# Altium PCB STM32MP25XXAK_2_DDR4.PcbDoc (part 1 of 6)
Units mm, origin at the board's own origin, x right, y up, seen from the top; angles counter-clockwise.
Board outline 120 x 79.6 mm, 4 copper layers (Top Layer, Signal Layer 1, Signal Layer 2, Bottom Layer), stack 1.614 mm thick; 243 components, 152 nets, 1304 pads, 784 vias.
Unrouted connection lines stored in the file: 6.
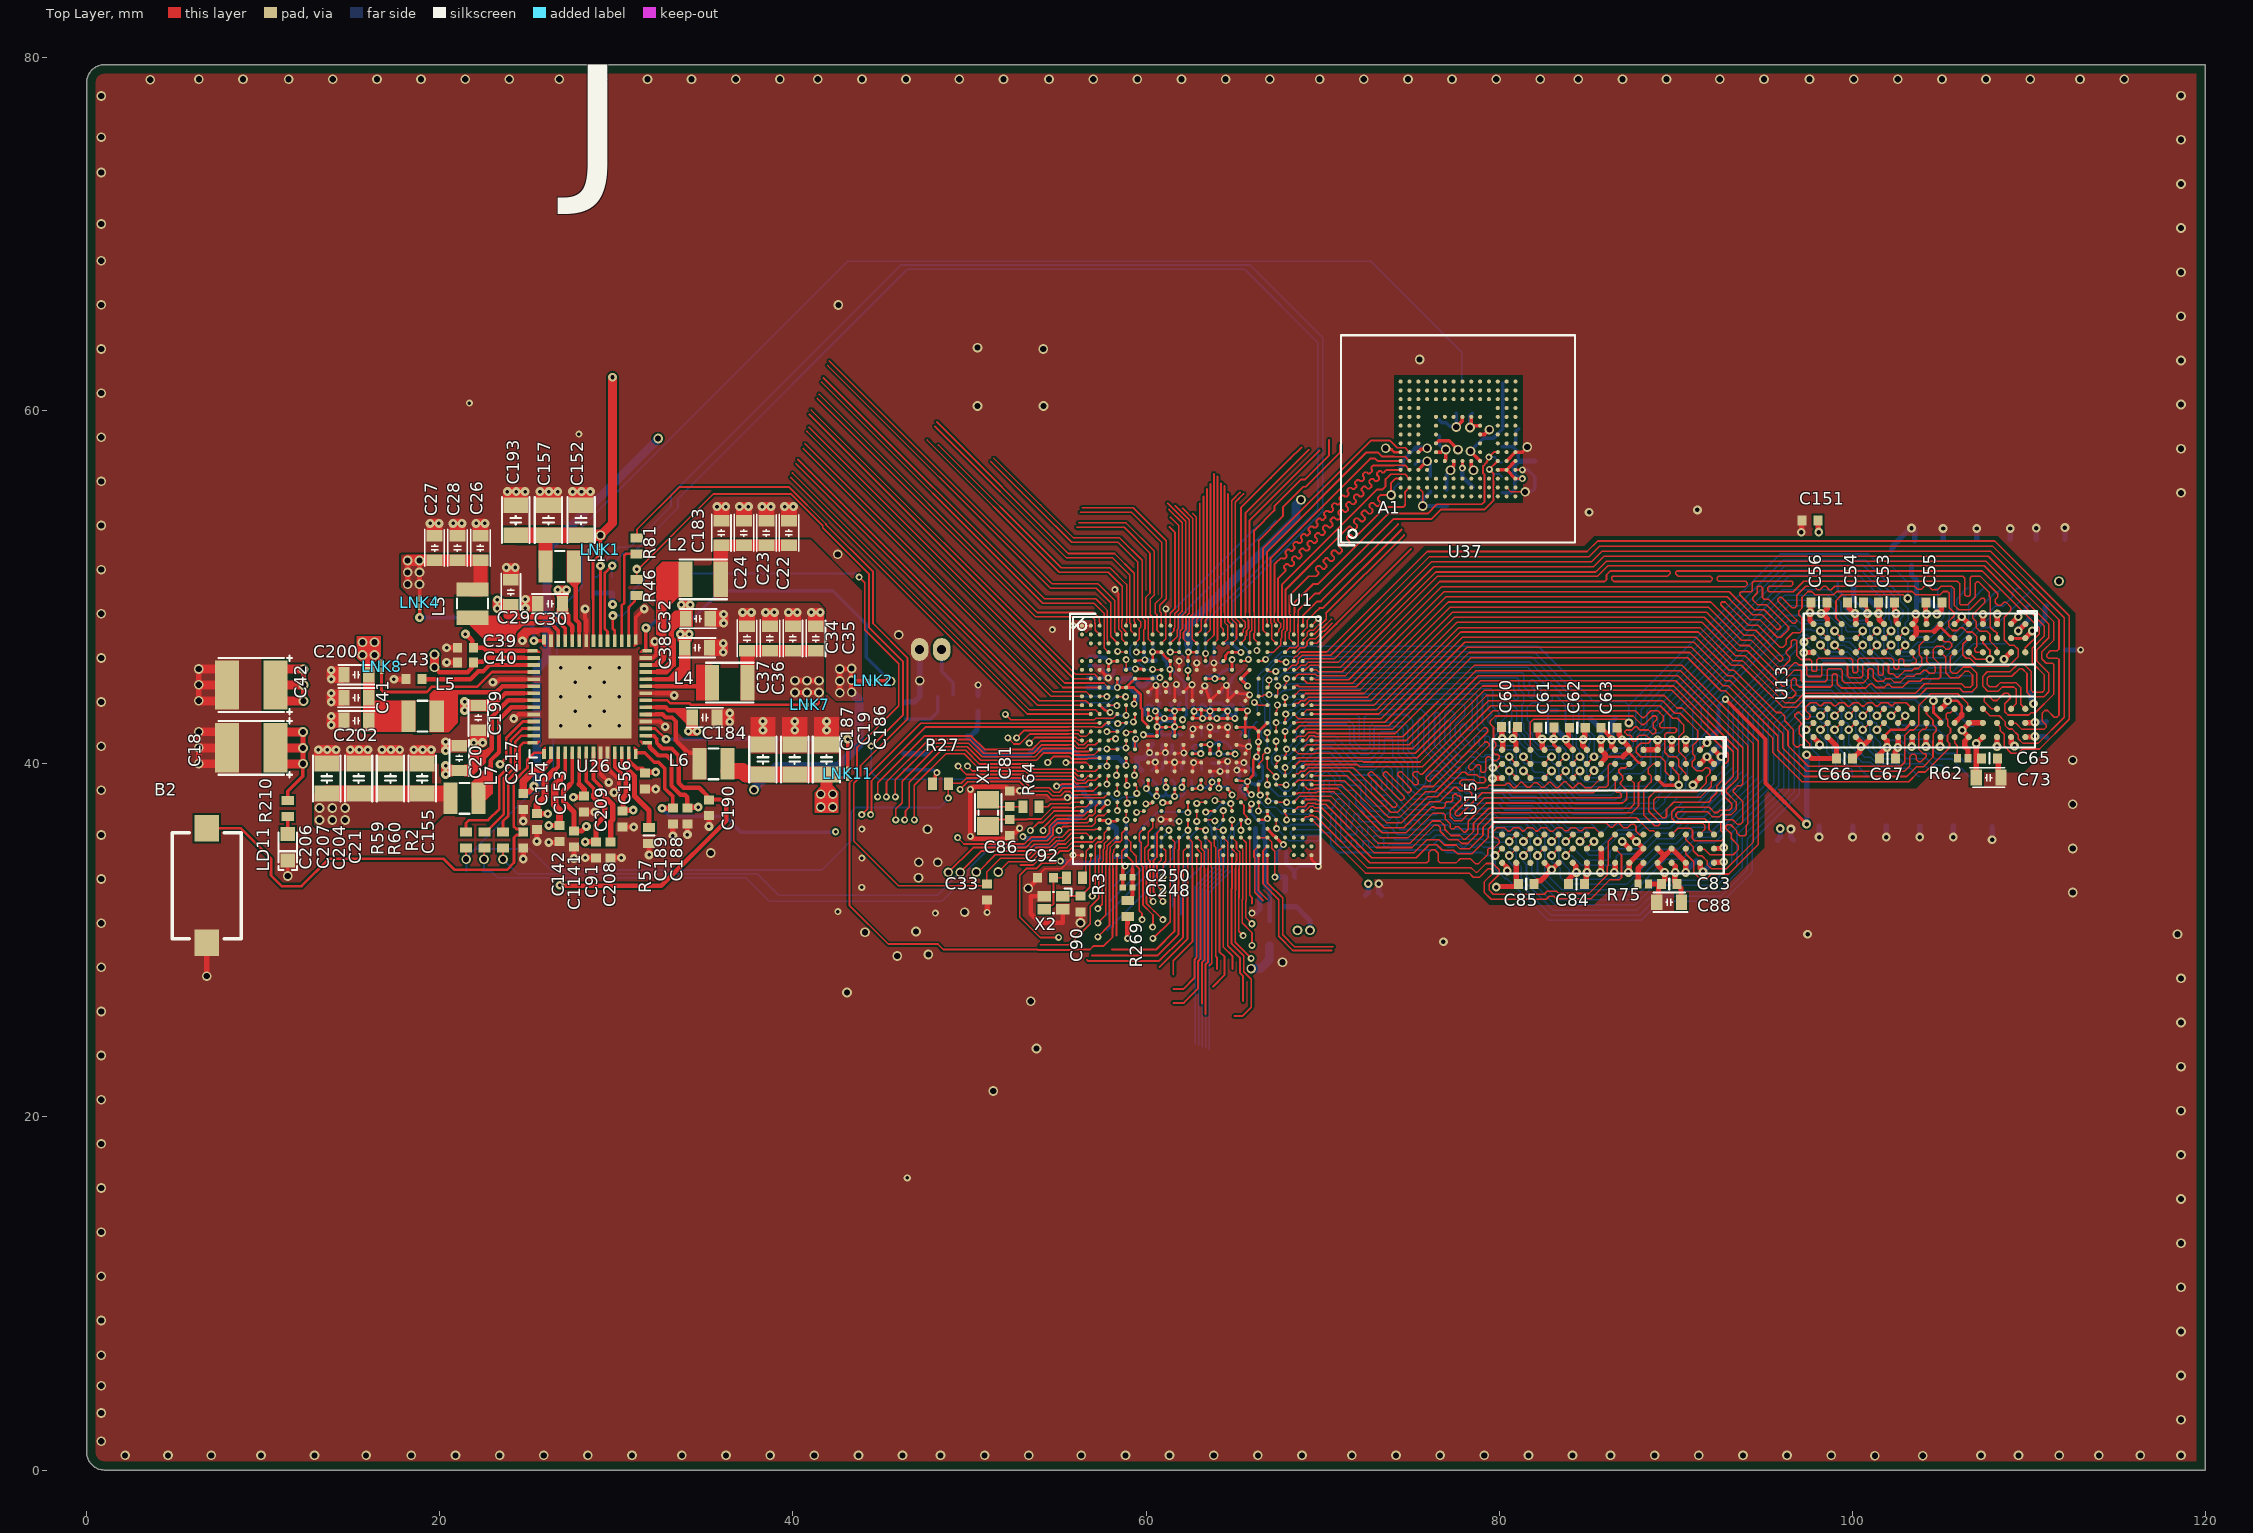
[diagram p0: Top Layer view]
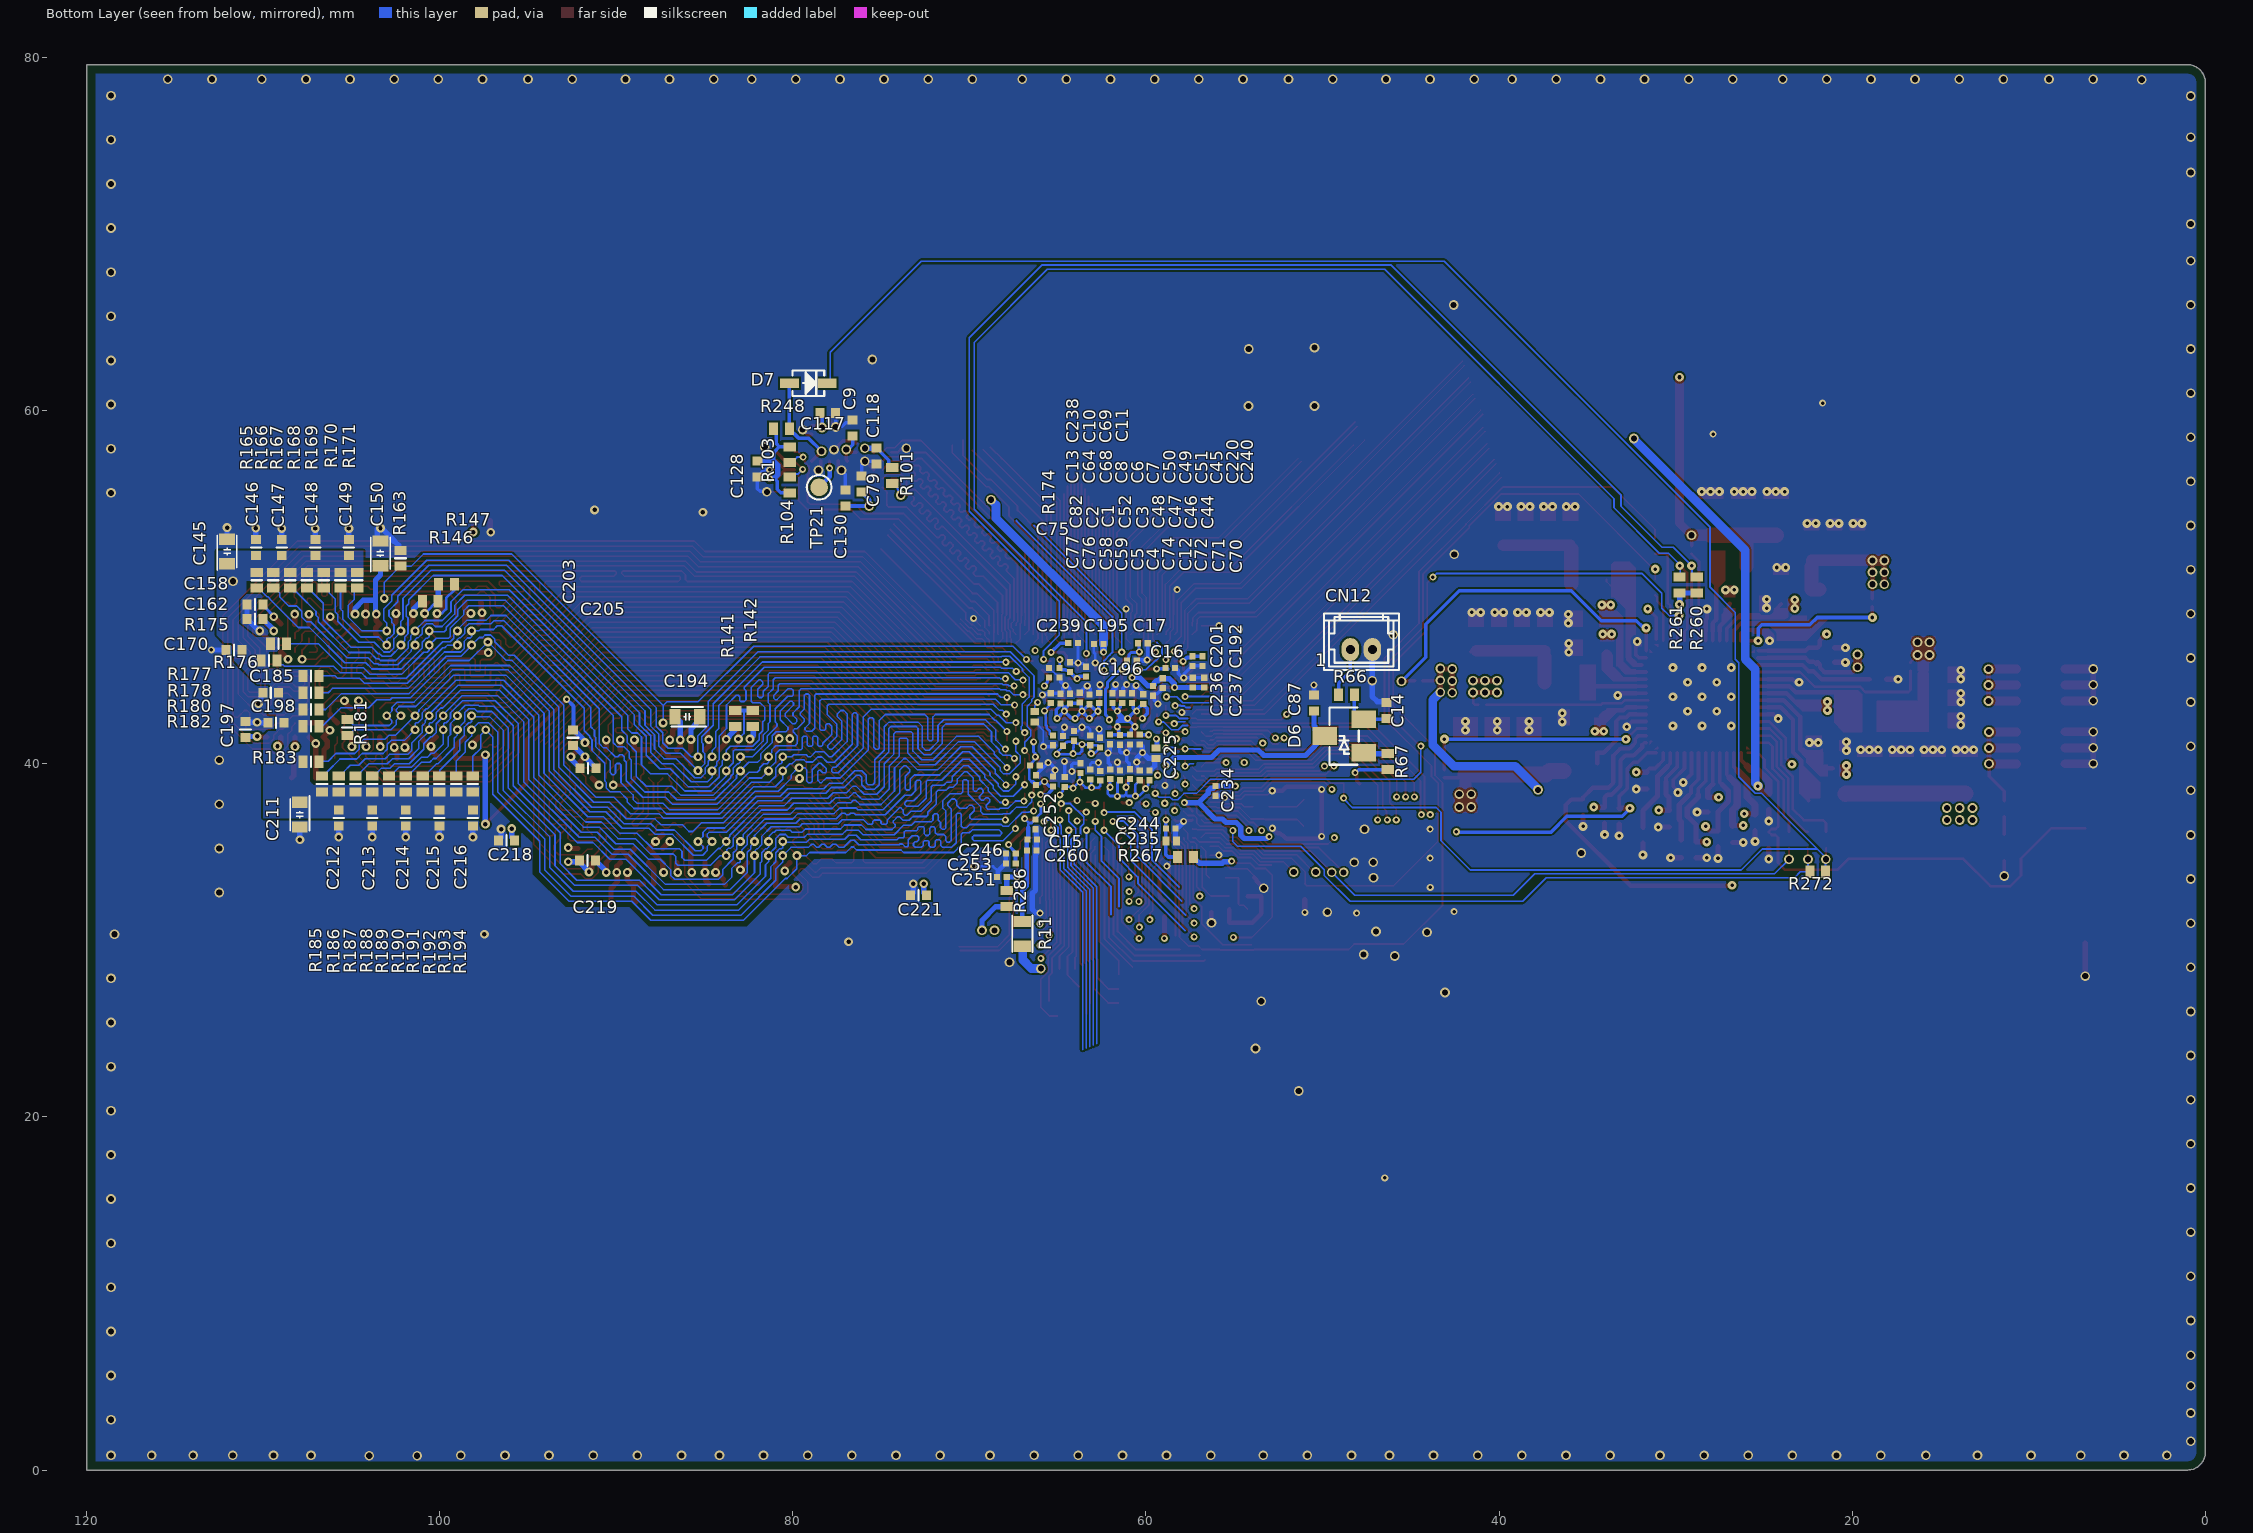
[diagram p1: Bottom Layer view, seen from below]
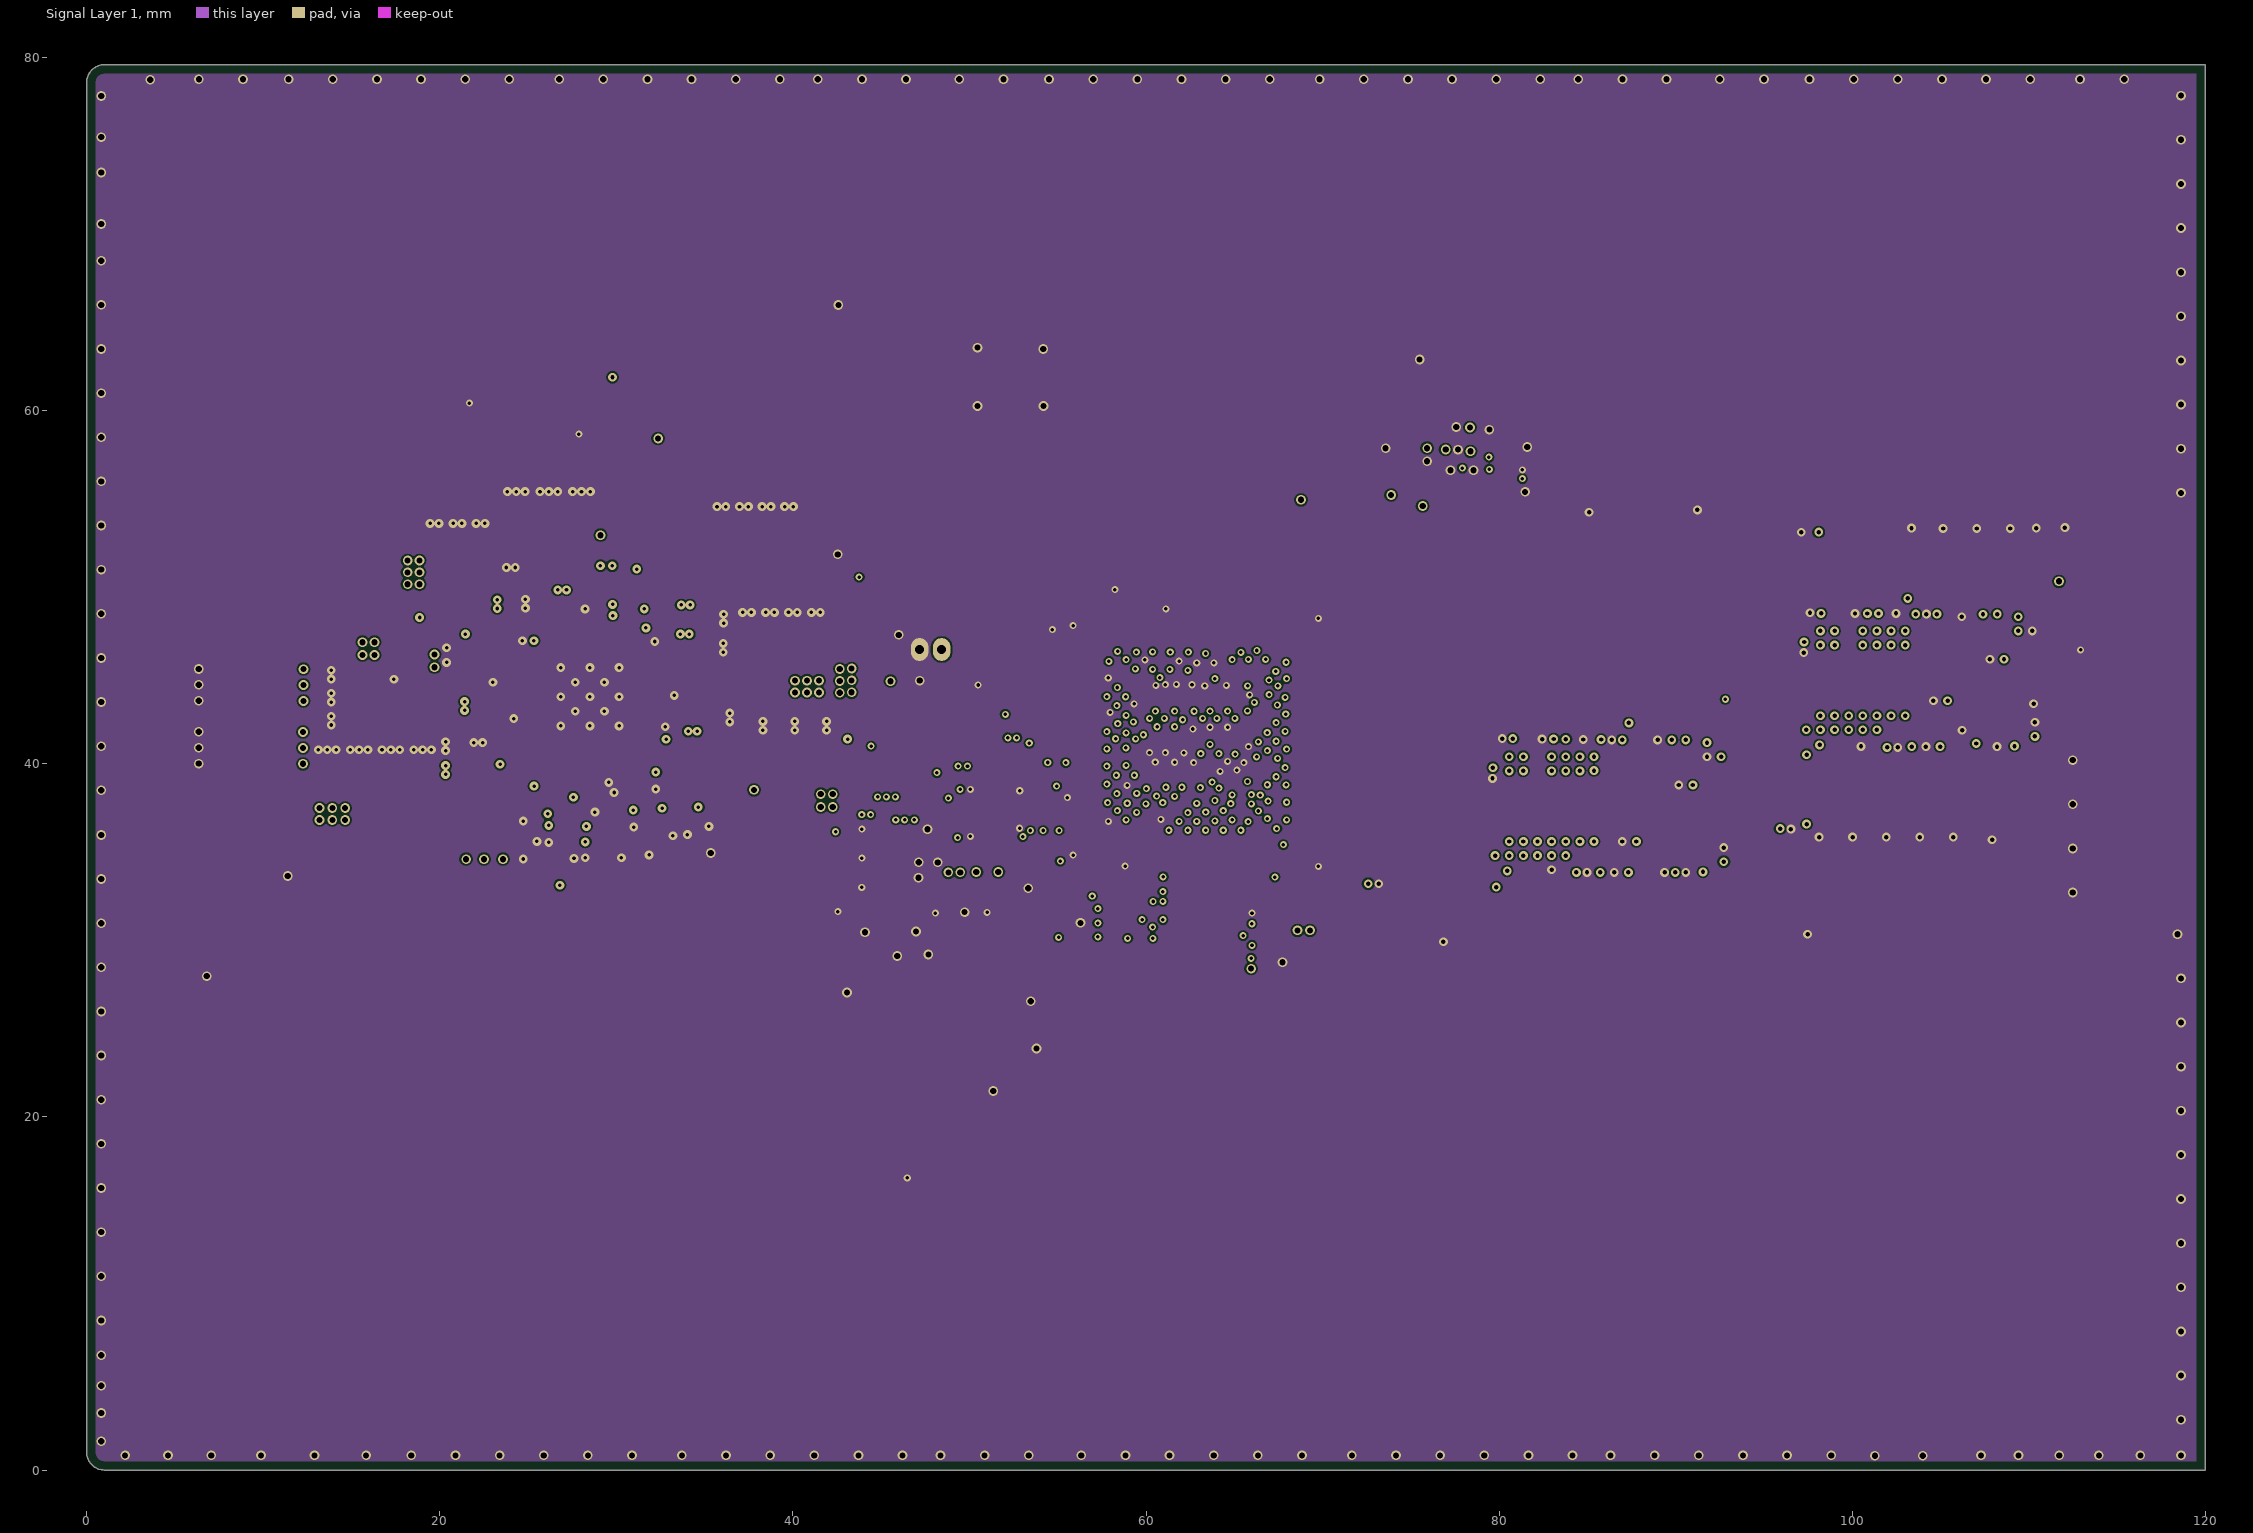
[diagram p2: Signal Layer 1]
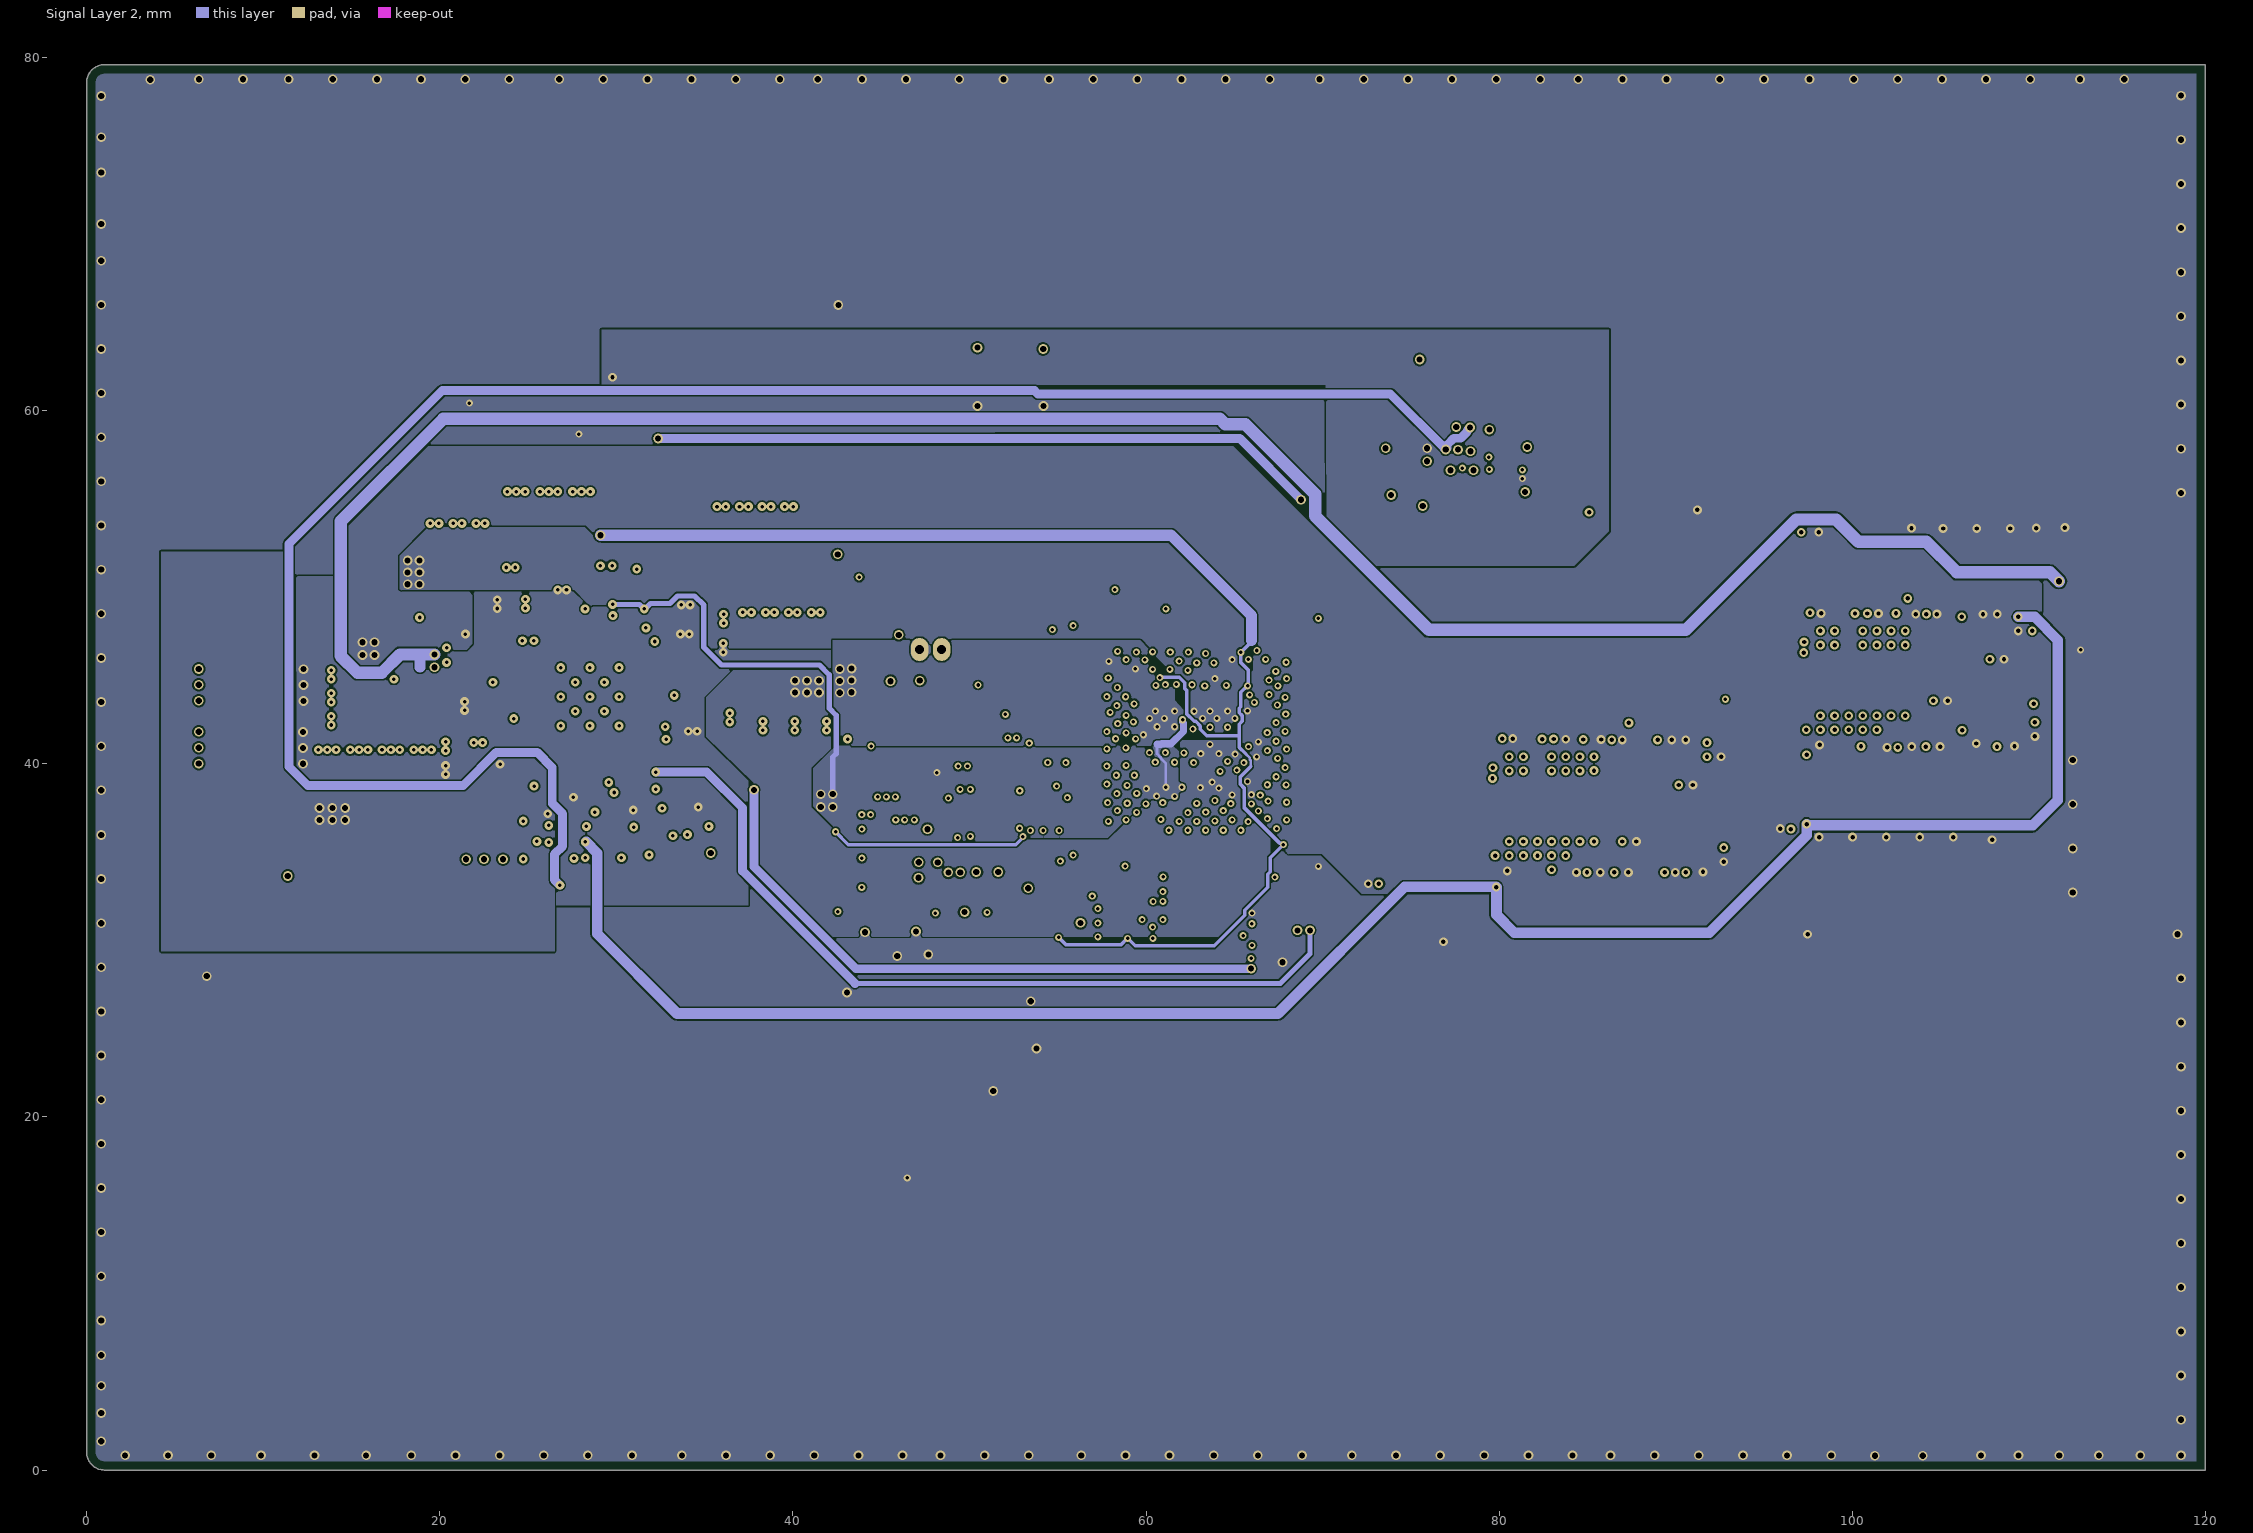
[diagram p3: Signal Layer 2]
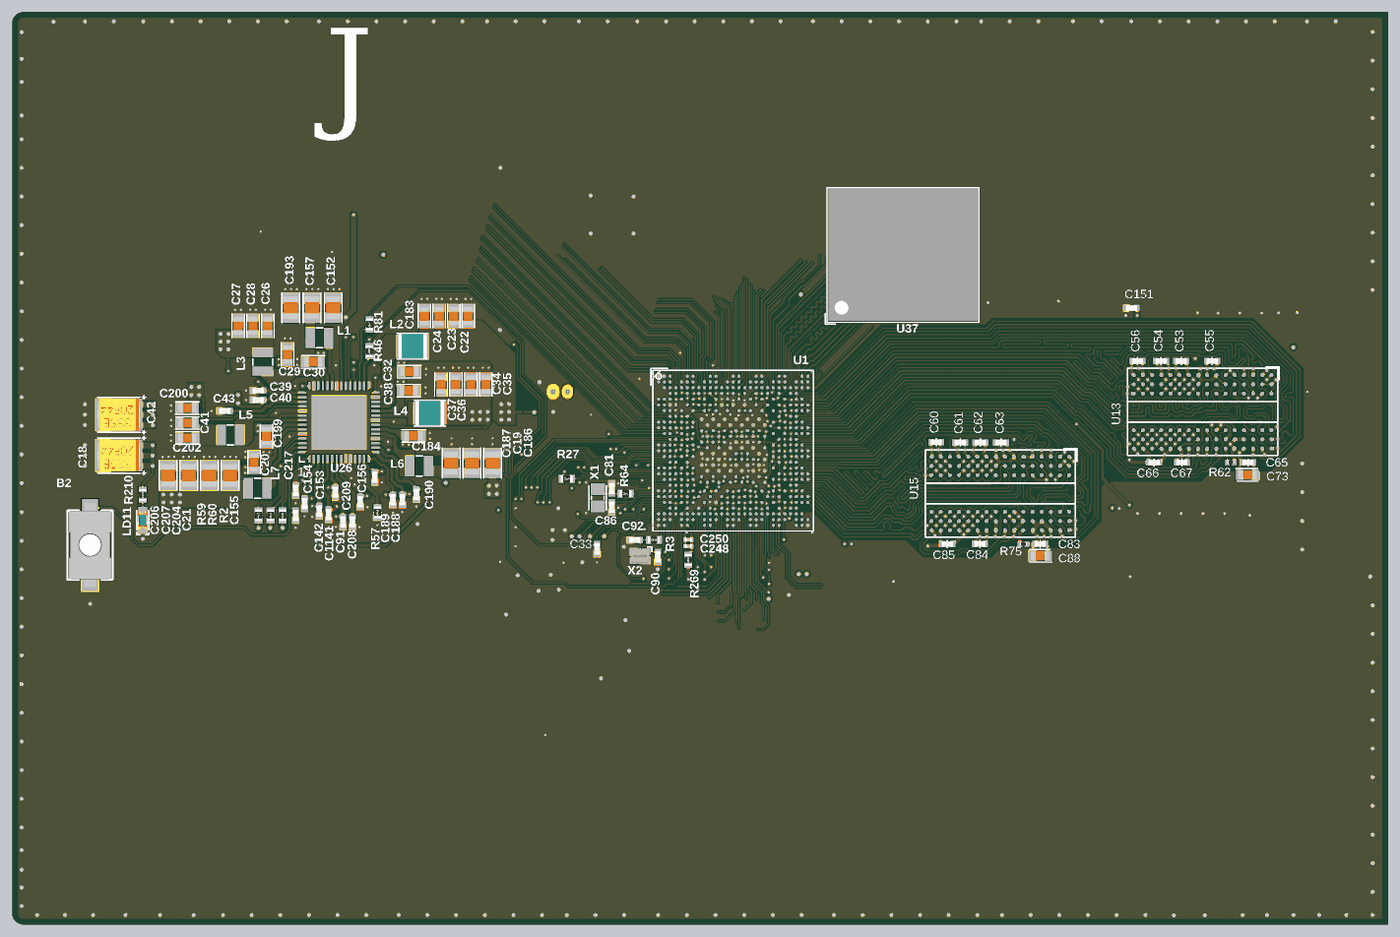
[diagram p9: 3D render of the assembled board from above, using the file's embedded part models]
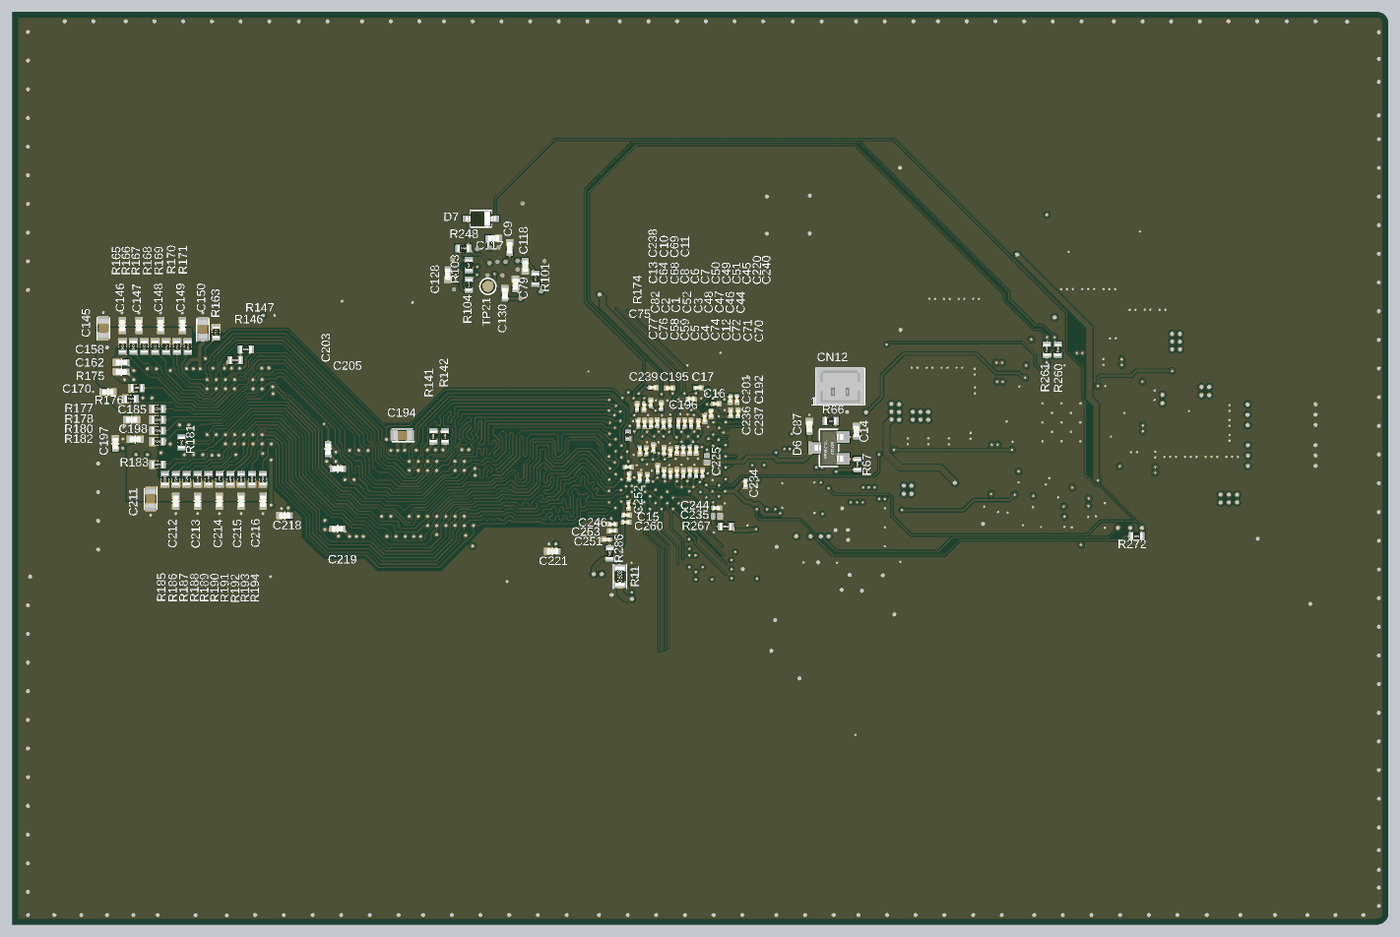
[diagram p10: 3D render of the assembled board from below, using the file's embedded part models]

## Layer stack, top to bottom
Top Solder: solder mask 0.025, Solder Resist, Dk 3.5
Top Layer: signal copper 0.037
Dielectric 1: prepreg 0.07, Dk 3.8
Signal Layer 1: signal copper 0.035
Dielectric 2: core 1.33, Dk 4.3
Signal Layer 2: signal copper 0.035
Dielectric 3: prepreg 0.07, Dk 3.8
Bottom Layer: signal copper 0.037
Bottom Solder: solder mask 0.025, Solder Resist, Dk 3.5

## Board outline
0,1 0,78.6 cw(c1,78.6) 1,79.6 120,79.6 120,0 1,0 cw(c1,1)

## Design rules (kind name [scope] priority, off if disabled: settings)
BoardOutlineClearance Silkscreen [OnLayer('Top Overlay') or OnLayer('Bottom Overlay')] p1: gap=0 ignorepadtopadclearanceinfootprint=FALSE
BoardOutlineClearance [All] p2: gap=0.5 ignorepadtopadclearanceinfootprint=FALSE
Clearance Clearance_Default [All] p1: gap=0.1 ignorepadtopadclearanceinfootprint=TRUE except(0: SMDPad-Hole Via-Hole; 0.09: Track-Track Track-SMDPad; 0.2: Arc-Arc Arc-Track Arc-Hole Track-Hole SMDPad-SMDPad THPad-Hole Fill-Hole Poly-Hole Region-Hole Text-Hole)
ComponentClearance [All] p1: gap=0.2 collisioncheckmode=3 verticalgap=0 showdistances=FALSE
DiffPairsRouting 100H [InDifferentialPairClass('100H')] p1: maxlimit=0.254 minlimit=0.16 mostfreqgap=0.16 toplayer_maxgap=0.16 toplayer_minwidth=0.09 toplayer_maxwidth=0.09 toplayer_prefwidth=0.09 midlayer1_minwidth=0.09 midlayer1_maxwidth=0.381 midlayer1_prefwidth=0.09 midlayer4_minwidth=0.09 midlayer4_maxwidth=0.381 midlayer4_prefwidth=0.09 bottomlayer_maxgap=0.16 bottomlayer_minwidth=0.09 bottomlayer_maxwidth=0.09 bottomlayer_prefwidth=0.09 impedanceprofiledriven=TRUE impedanceprofileid={628B3294-B84C-4222-8D8D-B3EA8745C43E} impedanceprofilevalue=100.000000 maxuncoupledlength=12.7
FanoutControl Fanout_BGA [IsBGA] p1: bgadir=Out bgaviamode=Closest fanoutstyle=Auto fanoutdirection=Alternating viagrid=0.025 // Fanout_BGA (Default Rule)
FanoutControl Fanout_LCC [IsLCC] p2: bgadir=Out bgaviamode=Closest fanoutstyle=Auto fanoutdirection=Alternating viagrid=0.025 // Fanout_LCC (Default Rule)
FanoutControl Fanout_SOIC [IsSOIC] p3: bgadir=Out bgaviamode=Closest fanoutstyle=Auto fanoutdirection=Alternating viagrid=0.025 // Fanout_SOIC (Default Rule)
FanoutControl Fanout_Small [(CompPinCount < 5)] p4: bgadir=Out bgaviamode=Closest fanoutstyle=Auto fanoutdirection=OutThenIn viagrid=0.025 // Fanout_Small (Default Rule)
FanoutControl Fanout_Default [All] p5: bgadir=Out bgaviamode=Closest fanoutstyle=Auto fanoutdirection=Alternating viagrid=0.025 // Fanout_Default (Default Rule)
HoleSize [All] p1: absolutevalues=TRUE maxlimit=10 minlimit=0.1 maxpercent=80.000 minpercent=20.000
HoleToHoleClearance [All] p1: gap=0.25 allowstackedmicrovias=TRUE
MinimumSolderMaskSliver MinimumSolderMaskSliver_SOLDER_BRIDGE [All vs HasFootprint('SOLDER-BRIDGE_R0603-0R')] p1: minsoldermaskwidth=0.07
MinimumSolderMaskSliver [All] p2: minsoldermaskwidth=0.075
NetAntennae [All] p1 off: netantennaetolerance=0
PlaneConnect [All] p1: planeconnectstyle=Direct reliefexpansion=0.508 reliefentries=4 reliefconductorwidth=0.21 reliefairgap=0.21
PolygonConnect PolygonConnect_Default [All] p1: connectstyle=Direct reliefconductorwidth=0.25 reliefentries=4 polygonreliefangle="90 Angle" airgapwidth=0.25
RoomDefinition RoomDefinition_eMMC [False] p1: confinementstyle=ConfineIn formatcopy=TRUE lockcomponents=FALSE outline 74.056,62.109 81.346,62.109 81.346,54.705 74.056,54.705
RoomDefinition RoomDefinition_DDR [False] p2: confinementstyle=ConfineIn formatcopy=TRUE lockcomponents=FALSE outline 79.028,49.26 90.8,49.26 90.8,33.46 79.028,33.46
RoomDefinition U_PMIC [InComponentClass('U_PMIC')] p3: confinementstyle=ConfineIn formatcopy=TRUE lockcomponents=FALSE outline 55.625,48.575 70.125,48.575 70.125,34.075 55.625,34.075
RoutingVias RoutingVias_Default [InDrillLayerPair('Top Layer - Bottom Layer')] p1: holewidth=0.15 width=0.4 viastyle="Through Hole" minholewidth=0.15 minwidth=0.4 maxholewidth=0.35 maxwidth=0.6 useviatemplates=TRUE viatemplateguid#1={8082EAB8-D593-4669-9C8E-234CD125C595} viatemplateguid#2={4A52CD78-2857-4DB8-ADAE-B449967CBE18} viatemplateguid#3={0C56A9B8-CF93-463B-97D5-BDCC265789B0} viatemplateguid#4={9EEAC5F1-1464-4AAC-8BE4-C1C0A6092F06} viatemplateguid#5={9A8C30F8-C6A2-4C13-8E9B-1F9A2318E40D} viatemplateguid#6={9F28DA9E-6088-4B56-A5CF-E6C86A3E97F7} viatemplatename#1=v40h20m0mx0 viatemplatename#2=v40h20m0mx0(1) viatemplatename#3=v50h20m25 viatemplatename#4=v50h25m0mx0 viatemplatename#5=v50h25m30mx30 viatemplatename#6=v55h35m40mx40
ShortCircuit [All] p1 off: allowed=FALSE
SilkToSilkClearance [All] p1: silktosilkclearance=0.2
SilkToSolderMaskClearance [IsPad] p1: minsilkscreentomaskgap=0.015 clearancetoexposedcopper=TRUE
SolderMaskExpansion [All] p1: expansion=0.1 istentingtop=FALSE
UnRoutedNet [All] p1 off:
ViasUnderSMD [InPadClass('PC_VIAS-IN-PAD_OK')] p1: allowed=TRUE
Width Width_SINGLE_50R [InNetClass('50H')] p1: maxlimit=0.199 minlimit=0.078 preferedwidth=0.199 toplayer_minwidth=0.09 toplayer_maxwidth=0.11 toplayer_prefwidth=0.11 bottomlayer_minwidth=0.11 bottomlayer_maxwidth=0.11 bottomlayer_prefwidth=0.11 impedanceprofiledriven=TRUE impedanceprofileid={152E730A-FDA4-4006-BF82-0EE0D5C1A339} impedanceprofilevalue=50.000000 minimp=50.000000 maximp=50.000000 favimp=50.000000
Width Width_SINGLE_DDR_55R [InNetClass('55H')] p2: maxlimit=0.199 minlimit=0.078 preferedwidth=0.199 toplayer_minwidth=0.09 toplayer_maxwidth=0.09 toplayer_prefwidth=0.09 bottomlayer_minwidth=0.09 bottomlayer_maxwidth=0.09 bottomlayer_prefwidth=0.09 impedanceprofiledriven=TRUE impedanceprofileid={D5948A69-504E-4D29-B9E5-77B49DDD78E4} impedanceprofilevalue=55.000000 minimp=50.000000 maximp=50.000000 favimp=50.000000
Width Width_Default [InNet('GND')] p3: maxlimit=10 minlimit=0.09 preferedwidth=0.3
14 further rules are at their usual default settings.

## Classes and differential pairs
component class U_2_DDR4_16bits: C53 C54 C55 C56 C60 C61 C62 C63 C65 C66 C67 C73 C83 C84 C85 C88 C145 C146 C147 C148 C149 C150 C151 C158 C162 C170 C185 C194 C197 C198 C203 C205 C211 C212 C213 C214 C215 C216 C218 C219 C221 R62 R75 R141 R142 R146 R147 R163 R165 R166 R167 R168 R169 R170 R171 R174 R175 R176 R177 R178 R180 R181 R182 R183 R185 R186 R187 R188 R189 R190 R191 R192 R193 R194 U13 U15
net class 55H: DDR_A0 DDR_A1 DDR_A2 DDR_A3 DDR_A4 DDR_A5 DDR_A6 DDR_A7 DDR_A8 DDR_A9 DDR_A10 DDR_A11 DDR_A12 DDR_A13 DDR_BA0 DDR_BA1 DDR_CASN DDR_CKE DDR_CSN DDR_DQ0 DDR_DQ1 DDR_DQ2 DDR_DQ3 DDR_DQ4 DDR_DQ5 DDR_DQ6 DDR_DQ7 DDR_DQ8 DDR_DQ9 DDR_DQ10 DDR_DQ11 DDR_DQ12 DDR_DQ13 DDR_DQ14 DDR_DQ15 DDR_DQ16 DDR_DQ17 DDR_DQ18 DDR_DQ19 DDR_DQ20 DDR_DQ21 DDR_DQ22 DDR_DQ23 DDR_DQ24 DDR_DQ25 DDR_DQ26 DDR_DQ27 DDR_DQ28 DDR_DQ29 DDR_DQ30 DDR_DQ31 DDR_DQM0 DDR_DQM1 DDR_DQM2 DDR_DQM3 DDR_ODT DDR_RASN DDR_RESETN DDR_WEN
differential pair class 100H: DDR_CLK DDR_DQS0 DDR_DQS1 DDR_DQS2 DDR_DQS3
net class eMMC.SDMMC2_D[0..7]: eMMC.SDMMC2_CK eMMC.SDMMC2_CMD eMMC.SDMMC2_D0 eMMC.SDMMC2_D1 eMMC.SDMMC2_D2 eMMC.SDMMC2_D3 eMMC.SDMMC2_D4 eMMC.SDMMC2_D5 eMMC.SDMMC2_D6 eMMC.SDMMC2_D7
component class U_eMMC: C9 C79 C117 C118 C128 C130 D7 R101 R103 R104 R248 TP21 U37
component class "U_STM32MP25XXAK I_Os": C33 C81 C86 C90 C92 R3 R27 R64 R260 R261 R272 U1 X1 X2
component class "U_STM32MP25XXAK Power": C1 C2 C3 C4 C5 C6 C7 C8 C10 C11 C12 C13 C14 C15 C16 C17 C44 C45 C46 C47 C48 C49 C50 C51 C52 C58 C59 C64 C68 C69 C70 C71 C72 C74 C75 C76 C77 C82 C87 C192 C195 C196 C201 C220 C225 C234 C235 C236 C237 C238 C239 C240 C244 C246 C248 C250 C251 C252 C253 C260 CN12 D6 R11 R66 R67 R267 R269 R286
component class U_PMIC: B2 C18 C19 C20 C21 C22 C23 C24 C26 C27 C28 C29 C30 C32 C34 C35 C36 C37 C38 C39 C40 C41 C42 C43 C91 C142 C152 C153 C154 C155 C156 C157 C183 C184 C186 C187 C188 C189 C190 C193 C199 C200 C202 C204 C206 C207 C208 C209 C217 C1141 L1 L2 L3 L4 L5 L6 L7 LD11 LNK1 LNK2 LNK4 LNK7 LNK8 LNK11 R2 R46 R57 R59 R60 R81 R210 U26
differential pair DDR_CLK: +DDR_CLK_P -DDR_CLK_N
differential pair DDR_DQS3: +DDR_DQS3_P -DDR_DQS3_N
differential pair DDR_DQS1: +DDR_DQS1_P -DDR_DQS1_N
differential pair DDR_DQS2: +DDR_DQS2_P -DDR_DQS2_N
differential pair DDR_DQS0: +DDR_DQS0_P -DDR_DQS0_N

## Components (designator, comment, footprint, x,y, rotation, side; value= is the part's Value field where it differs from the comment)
B2 "SW_PUSH_SMD_2P" SWI_WE_434121025816 6.795,33.104 r90 top value=434121025816
C1 "1uF" C0201_MURATA_GRM033_H0P3 64.083,41.581 r270 bottom
C2 "1uF" C0201_MURATA_GRM033_H0P3 64.705,41.304 r270 bottom
C3 "1uF" C0201_MURATA_GRM033_H0P3 62.6,41.2 r270 bottom
C4 "1uF" C0201_MURATA_GRM033_H0P3 62.592,39.328 r270 bottom
C5 "1uF" C0201_MURATA_GRM033_H0P3 63.154,39.397 r270 bottom
C6 "1uF" C0201_MURATA_GRM033_H0P3 63.2,43.65 r90 bottom
C7 "1uF" C0201_MURATA_GRM033_H0P3 62.65,43.73 r270 bottom
C8 "1uF" C0201_MURATA_GRM033_H0P3 63.75,43.75 r90 bottom
C9 "Capacitor" C0402 76.615,59.03 r270 bottom value=100nF
C10 "1uF" C0201_MURATA_GRM033_H0P3 64.9,45.16 r90 bottom
C11 "1uF" C0201_MURATA_GRM033_H0P3 63.4,45.225 r270 bottom
C12 "1uF" C0201_MURATA_GRM033_H0P3 61.467,39.349 r90 bottom
C13 "1uF" C0201_MURATA_GRM033_H0P3 65.4,43.725 r270 bottom
C14 "Capacitor" C0402 46.382,43.015 r270 bottom value=2.2uF
C15 "Capacitor" C0201_MURATA_GRM033_H0P3 66.446,35.716 r0 bottom value=1uF
C16 "Capacitor" C0201_MURATA_GRM033_H0P3 58.625,45.425 r0 bottom value=100nF
C17 "Capacitor" C0201_MURATA_GRM033_H0P3 60.177,46.829 r0 bottom value=100nF
C18 "Cap_POL_TANA" CPOL_TCJ-B_1210_H210 9.311,40.906 r180 top value=100uF
C19 "Capacitor" C0805 40.1,40.25 r270 top value=22uF
C20 "Capacitor" C0603 21.1,40.325 r270 top value=10uF
C21 "Capacitor" C0805 19,39.173 r270 top value=22uF
C22 "Capacitor" C0603 39.775,53.075 r270 top value=22uF
C23 "Capacitor" C0603 38.5,53.075 r270 top value=22uF
C24 "Capacitor" C0603 37.225,53.075 r270 top value=22uF
C26 "Capacitor" C0603 22.3,52.225 r270 top value=22uF
C27 "Capacitor" C0603 19.7,52.225 r270 top value=22uF
C28 "Capacitor" C0603 21,52.225 r270 top value=22uF
C29 "Capacitor" C0603 24.025,49.725 r270 top value=10uF
C30 "Capacitor" C0603 26.25,49.075 r0 top value=10uF
C32 "Capacitor" C0603 34.625,48.225 r180 top value=10uF
C33 "Capacitor" C0402 51,32.75 r90 top value=10nF
C34 "Capacitor" C0603 40,47.1 r270 top value=22uF
C35 "Capacitor" C0603 41.3,47.1 r270 top value=22uF
C36 "Capacitor" C0603 38.7,47.1 r270 top value=22uF
C37 "Capacitor" C0603 37.4,47.1 r270 top value=22uF
C38 "Capacitor" C0603 34.575,46.575 r180 top value=10uF
C39 "Capacitor" C0402 21.445,46.575 r0 top value=10uF
C40 "Capacitor" C0402 21.445,45.75 r0 top value=10uF
C41 "Capacitor" C0603 15.275,43.75 r0 top value=22uF
C42 "Cap_POL_TANA" CPOL_TCJ-B_1210_H210 9.311,44.468 r180 top value=100uF
C43 "Capacitor" C0402 18.535,44.8 r0 top value=1uF
C44 "1uF" C0201_MURATA_GRM033_H0P3 60.351,41.38 r270 bottom
C45 "1uF" C0201_MURATA_GRM033_H0P3 60.16,43.67 r270 bottom
C46 "1uF" C0201_MURATA_GRM033_H0P3 60.915,41.38 r90 bottom
C47 "1uF" C0201_MURATA_GRM033_H0P3 61.476,41.356 r270 bottom
C48 "1uF" C0201_MURATA_GRM033_H0P3 62.038,41.382 r90 bottom
C49 "1uF" C0201_MURATA_GRM033_H0P3 61.35,43.725 r270 bottom
C50 "1uF" C0201_MURATA_GRM033_H0P3 61.9,43.725 r270 bottom
C51 "1uF" C0201_MURATA_GRM033_H0P3 60.8,43.725 r270 bottom
C52 "1uF" C0201_MURATA_GRM033_H0P3 63.162,41.332 r270 bottom
C53 "Capacitor" C0402 101.95,49.15 r180 top value=100nF
C54 "Capacitor" C0402 100.18,49.15 r0 top value=100nF
C55 "Capacitor" C0402 104.63,49.15 r0 top value=100nF
C56 "Capacitor" C0402 98.13,49.145 r0 top value=100nF
C58 "1uF" C0201_MURATA_GRM033_H0P3 64.607,38.972 r270 bottom
C59 "1uF" C0201_MURATA_GRM033_H0P3 63.714,39.761 r270 bottom
C60 "Capacitor" C0402 80.581,42.082 r0 top value=100nF
C61 "Capacitor" C0402 82.665,42.05 r0 top value=100nF
C62 "Capacitor" C0402 84.431,42.048 r180 top value=100nF
C63 "Capacitor" C0402 86.22,42.048 r0 top value=100nF
C64 "1uF" C0201_MURATA_GRM033_H0P3 64.85,43.7 r270 bottom
C65 "Capacitor" C0402 107.771,40.313 r180 top value=100nF
C66 "Capacitor" C0402 99.568,40.299 r180 top value=100nF
C67 "Capacitor" C0402 101.999,40.307 r180 top value=100nF
C68 "1uF" C0201_MURATA_GRM033_H0P3 64.3,43.7 r270 bottom
C69 "1uF" C0201_MURATA_GRM033_H0P3 64.305,45.477 r270 bottom
C70 "1uF" C0201_MURATA_GRM033_H0P3 59.805,39.35 r90 bottom
C71 "1uF" C0201_MURATA_GRM033_H0P3 60.355,39.35 r270 bottom
C72 "1uF" C0201_MURATA_GRM033_H0P3 60.905,39.423 r270 bottom
C73 "Capacitor" C0603 107.731,39.223 r180 top value=10uF
C74 "1uF" C0201_MURATA_GRM033_H0P3 62.03,39.408 r270 bottom
C75 "1uF" C0201_MURATA_GRM033_H0P3 66.29,39.9 r0 bottom
C76 "1uF" C0201_MURATA_GRM033_H0P3 65.275,39 r270 bottom
C77 "1uF" C0201_MURATA_GRM033_H0P3 66.225,39.075 r90 bottom
C79 "Capacitor" C0402 76.11,55.855 r270 bottom value=2.2uF
C81 "Capacitor" C0402 52.285,38.025 r90 top value=6.8pF
C82 "1uF" C0201_MURATA_GRM033_H0P3 65.26,41.325 r90 bottom
C83 "Capacitor" C0402 89.636,33.195 r0 top value=100nF
C84 "Capacitor" C0402 84.377,33.198 r180 top value=100nF
C85 "Capacitor" C0402 81.541,33.193 r180 top value=100nF
C86 "Capacitor" C0402 52.285,36.4 r270 top value=6.8pF
C87 "" C0402 50.485,43.438 r270 bottom value=100nF
C88 "Capacitor" C0603 89.629,32.165 r0 top value=10uF
C90 "Capacitor" C0402 56.293,32.06 r90 top value=6.8pF
C91 "Capacitor" C0402 28.85,35.13 r270 top value=4.7uF
C92 "Capacitor" C0402 54.309,33.546 r180 top value=6.8pF
C117 "Capacitor" C0402 78.025,59.864 r0 bottom value=2.2uF
C118 "Capacitor" C0402 75.26,57.43 r90 bottom value=100nF
C128 "Capacitor" C0402 82.015,56.705 r90 bottom value=2.2uF
C130 "Capacitor" C0402 77.027,55.055 r270 bottom value=100nF
C142 "Capacitor" C0402 26.775,36.06 r270 top value=4.7uF
C145 "Capacitor" C0603 112.053,52.028 r270 bottom locked value=22uF
C146 "Capacitor" C0402 110.403,52.252 r270 bottom value=100nF
C147 "Capacitor" C0402 108.953,52.252 r270 bottom value=100nF
C148 "Capacitor" C0402 107.053,52.252 r270 bottom value=100nF
C149 "Capacitor" C0402 105.153,52.252 r270 bottom value=100nF
C150 "Capacitor" C0603 103.363,51.928 r270 bottom value=10uF
C151 "Capacitor" C0402 97.605,53.774 r0 top value=100nF
C152 "Capacitor" C0805 28,53.8 r270 top value=22uF
C153 "Capacitor" C0402 28.175,37.72 r90 top value=1uF
C154 "Capacitor" C0402 25.5,36.725 r90 top value=1uF
C155 "Capacitor" C0402 24.727,35.695 r90 top value=10nF
C156 "Capacitor" C0402 31.625,39.02 r90 top value=4.7uF
C157 "Capacitor" C0805 26.15,53.8 r270 top value=22uF
C158 "Capacitor" C0402 110.478,49.027 r180 bottom value=100nF
C162 "Capacitor" C0402 110.478,48.202 r180 bottom value=100nF
C170 "Capacitor" C0402 111.653,46.453 r180 bottom locked value=100nF
C183 "Capacitor" C0603 35.95,53.075 r270 top value=22uF
C184 "Capacitor" C0603 34.997,42.625 r180 top value=10uF
C185 "Capacitor" C0402 109.578,44.027 r180 bottom value=100nF
C186 "Capacitor" C0805 41.9,40.25 r270 top value=22uF
C187 "Capacitor" C0805 38.3,40.25 r270 top value=22uF
C188 "Capacitor" C0402 34.025,37.04 r90 top value=1uF
C189 "Capacitor" C0402 33.2,37.04 r90 top value=4.7uF
C190 "Capacitor" C0402 35.25,37.515 r270 top value=4.7uF
C192 "Capacitor" C0201_MURATA_GRM033_H0P3 56.8,45.825 r90 bottom value=100nF
C193 "Capacitor" C0805 24.3,53.8 r270 top value=22uF
C194 "Capacitor" C0603 85.98,42.67 r180 bottom value=10uF
C195 "Capacitor" C0201_MURATA_GRM033_H0P3 62.675,46.787 r180 bottom value=100nF
C196 "Capacitor" C0201_MURATA_GRM033_H0P3 60.8,45.85 r0 bottom value=100nF
C197 "Capacitor" C0402 111.003,41.952 r270 bottom value=100nF
C198 "Capacitor" C0402 109.278,42.327 r180 bottom value=100nF
C199 "Capacitor" C0603 22.175,42.6 r90 top value=10uF
C200 "Capacitor" C0603 15.275,45.05 r0 top value=22uF
C201 "Capacitor" C0201_MURATA_GRM033_H0P3 57.375,45.825 r90 bottom value=100nF
C202 "Capacitor" C0603 15.275,42.45 r0 top value=22uF
C203 "Capacitor" C0402 92.453,41.477 r90 bottom value=100nF
C204 "Capacitor" C0805 17.2,39.173 r270 top value=22uF
C205 "Capacitor" C0402 91.603,39.752 r0 bottom value=100nF
C206 "Capacitor" C0805 13.6,39.173 r270 top value=22uF
C207 "Capacitor" C0805 15.4,39.173 r270 top value=22uF
C208 "Capacitor" C0402 29.675,35.13 r270 top value=4.7uF
C209 "Capacitor" C0402 30.35,36.87 r90 top value=4.7uF
C211 "Capacitor" C0603 107.928,37.127 r90 bottom value=22uF
C212 "Capacitor" C0402 105.728,36.927 r90 bottom value=100nF
C213 "Capacitor" C0402 103.828,36.927 r90 bottom value=100nF
C214 "Capacitor" C0402 101.928,36.927 r90 bottom value=100nF
C215 "Capacitor" C0402 100.028,36.927 r90 bottom value=100nF
C216 "Capacitor" C0402 98.128,36.927 r90 bottom value=100nF
C217 "Capacitor" C0402 24.725,37.87 r270 top value=4.7uF
C218 "Capacitor" C0402 96.23,35.668 r180 bottom value=100nF
C219 "Capacitor" C0402 91.628,34.527 r0 bottom value=100nF
C220 "Capacitor" C0201_MURATA_GRM033_H0P3 59.609,44.131 r90 bottom value=100nF
C221 "Capacitor" C0402 72.889,32.556 r180 bottom locked value=100nF
C225 "Capacitor" C0201_H0P5 59.425,40.6 r90 bottom value=4.7uF
C234 "Capacitor" C0201_MURATA_GRM033_H0P3 56.064,38.473 r90 bottom value=100nF
C235 "Capacitor" C0201_H0P5 58.575,35.625 r0 bottom value=2.2uF
C236 "Capacitor" C0201_MURATA_GRM033_H0P3 57.35,44.6 r270 bottom value=100nF
C237 "Capacitor" C0201_MURATA_GRM033_H0P3 56.696,44.605 r270 bottom value=100nF
C238 "Capacitor" C0201_MURATA_GRM033_H0P3 65.5,45.158 r270 bottom value=100nF
C239 "Capacitor" C0201_MURATA_GRM033_H0P3 64.125,46.837 r0 bottom value=100nF
C240 "Capacitor" C0201_MURATA_GRM033_H0P3 59.05,44.575 r90 bottom value=100nF
C244 "Capacitor" C0201_MURATA_GRM033_H0P3 58.6,36.331 r0 bottom value=100nF
C246 "Capacitor" C0201_MURATA_GRM033_H0P3 67.65,34.925 r180 bottom value=100nF
C248 "Capacitor" C0201_MURATA_GRM033_H0P3 58.958,33.002 r0 top value=100nF
C250 "Capacitor" C0201_MURATA_GRM033_H0P3 58.958,33.572 r0 top value=1uF
C251 "Capacitor" C0201_MURATA_GRM033_H0P3 68.165,33.588 r180 bottom value=100nF
C252 "Capacitor" C0201_MURATA_GRM033_H0P3 66.255,36.575 r90 bottom value=1uF
C253 "Capacitor" C0201_MURATA_GRM033_H0P3 67.65,34.35 r180 bottom value=100nF
C260 "Capacitor" C0201_MURATA_GRM033_H0P3 66.473,35.094 r0 bottom value=1uF
C1141 "Capacitor" C0402 27.6,35.75 r270 top value=4.7uF
CN12 "" CON_MOLEX_53047-0210 47.8,46.475 r180 bottom value="Header 2x1"
D6 "DIODE_3P_DUAL_COMMON_CATHODE" DIO_SOT23 48.773,41.573 r90 bottom value=BAT54CFILM
D7 "BAT60JFILM" DIO_SOD323 79.125,61.563 r180 bottom
L1 "Inductor" IND_2016_MURATA_LQM2MPN2R2NG0 26.795,51.175 r180 top value=2.2uH
L2 "Inductor" IND_2520_TOKO_DFE252012P 34.915,50.45 r0 top value=0.68µH
L3 "Inductor" IND_2016_MURATA_LQM2MPN2R2NG0 21.85,49.075 r90 top value=0.68uH
L4 "Inductor" IND_2520_TOKO_DFE252012P 36.425,44.6 r0 top value=0.68µH
L5 "Inductor" IND_2016_MURATA_LQM2MPN2R2NG0 19.025,42.7 r180 top value=0.68uH
L6 "Inductor" IND_2016_MURATA_LQM2MPN2R2NG0 35.5,40 r0 top value=2.2uH
L7 "Inductor" IND_2016_MURATA_LQM2MPN2R2NG0 21.4,38.05 r180 top value=0.68uH
LD11 "LED_green" LED_0603_OSRAM_LG-Q396-PS-35_GREEN_1A2K_H0P4 11.386,35.272 r270 top value=GREEN
LNK1 "link_200" LINK200 29.1,52.123 r0 top
LNK2 "link_200" LINK200 44.541,44.7 r90 top
LNK4 "link_200" LINK200 18.85,49.125 r180 top
LNK7 "link_200" LINK200 40.95,43.35 r270 top
LNK8 "link_200" LINK200 16.7,45.498 r0 top
LNK11 "link_200" LINK200 43.1,39.44 r180 top
R2 "" R0402 23.58,35.695 r90 top value=0R
R3 "" R0402 55.959,33.546 r0 top value=0R
R11 "Resistor" R0603 67,30.375 r90 bottom value=0R
R27 "Resistor" R0402 48.355,38.872 r180 top value=10K
R46 "" R0402 31.15,49.998 r270 top value=0R
R57 "" R0402 31.85,35.95 r90 top value=0R
R59 "" R0402 21.48,35.695 r90 top value=0R
R60 "" R0402 22.53,35.695 r90 top value=0R
R62 "Resistor" R0201_H0P23 106.267,40.321 r180 top value=240R
R64 "" R0402 53.485,37.575 r180 top value=0R
R66 "Resistor" R0402 48.633,43.917 r180 bottom value=20R
R67 "Resistor" R0402 46.3,40.125 r270 bottom value=0R
R75 "Resistor" R0201_H0P23 88.175,33.193 r180 top value=240R
R81 "" R0402 31.163,52.348 r270 top value=0R
R101 "Resistor" R0402 74.375,56.325 r90 bottom value=10K
R103 "Resistor" R0402 80.171,57.511 r90 bottom value=10K
R104 "Resistor" R0402 80.175,55.805 r270 bottom value=10K
R141 "Resistor" R0402 83.268,42.573 r270 bottom value=1K
R142 "Resistor" R0402 82.268,42.575 r90 bottom value=1K
R146 "Resistor" R0402 100.545,49.217 r0 bottom value=1K
R147 "Resistor" R0402 99.632,50.175 r0 bottom value=1K
R163 "Resistor" R0402 102.228,51.648 r270 bottom value=10K
R165 "Resistor" R0402 110.378,50.402 r90 bottom value=56R
R166 "Resistor" R0402 109.428,50.402 r90 bottom value=56R
R167 "Resistor" R0402 108.478,50.402 r90 bottom value=56R
R168 "Resistor" R0402 107.528,50.402 r90 bottom value=56R
R169 "Resistor" R0402 106.578,50.402 r90 bottom value=56R
R170 "Resistor" R0402 105.628,50.402 r90 bottom value=56R
R171 "Resistor" R0402 104.678,50.402 r90 bottom value=56R
R174 "Resistor" R0201_H0P23 66.3,42.675 r90 bottom value=240R
R175 "Resistor" R0402 109.128,46.802 r0 bottom value=56R
R176 "Resistor" R0402 109.678,45.852 r0 bottom value=56R
R177 "Resistor" R0402 107.303,44.977 r0 bottom value=56R
R178 "Resistor" R0402 107.303,44.027 r0 bottom value=56R
R180 "Resistor" R0402 107.303,43.077 r0 bottom value=56R
R181 "Resistor" R0402 105.228,42.052 r90 bottom value=100R
R182 "Resistor" R0402 107.303,42.127 r0 bottom value=56R
R183 "Resistor" R0402 107.303,40.127 r0 bottom value=56R
R185 "Resistor" R0402 106.678,38.852 r270 bottom value=56R
R186 "Resistor" R0402 105.728,38.852 r270 bottom value=56R
R187 "Resistor" R0402 104.778,38.852 r270 bottom value=56R
R188 "Resistor" R0402 103.828,38.852 r270 bottom value=56R
R189 "Resistor" R0402 102.878,38.852 r270 bottom value=56R
R190 "Resistor" R0402 101.928,38.852 r270 bottom value=56R
R191 "Resistor" R0402 100.978,38.852 r270 bottom value=56R
R192 "Resistor" R0402 100.028,38.852 r270 bottom value=56R
R193 "Resistor" R0402 99.078,38.852 r270 bottom value=56R
R194 "Resistor" R0402 98.128,38.852 r270 bottom value=56R
R210 "Resistor" R0402 11.386,37.465 r270 top value=270R
R248 "Resistor" R0402 80.657,58.98 r0 bottom value=10K
R260 "Resistor" R0402 28.805,50.13 r270 bottom value=1K5
R261 "Resistor" R0402 29.78,50.13 r270 bottom value=1K5
R267 "" R0402 57.773,34.723 r180 bottom value=0R
R269 "" R0402 58.956,31.808 r90 top value=0R
R272 "Resistor" R0402 21.95,33.879 r0 bottom value=10K
R286 "" R0402 67.89,32.365 r90 bottom value=0R
TP21 "Test Point" TP_SMD_1MM 78.516,55.665 r90 bottom
U1 "STM32MP257FAK3" ICC_TFBGA424_14X14_P050_H1P20_CODE-B0A2 62.875,41.325 r0 top locked
U13 "MT40A1G16TB-062E IT:F" ICC_FBGA96_TB_7P5X13_P080 103.805,44.72 r270 top locked
U15 "MT40A1G16TB-062E IT:F" ICC_FBGA96_TB_7P5X13_P080 86.174,37.597 r270 top
U26 "STPMIC25APQR" ICC_QFN56-EPAD_6P5X6P5_P040 28.5,43.8 r90 top
U37 "eMMC_THGBMTG5D1LBAIL" ICC_P-WFBGA153_13X11P5_P050 77.675,58.405 r0 top value=THGBMTG5D1LBAIL
X1 "XTAL_2_PINS" CRY_NX2012SA_2P 51.059,37.225 r270 top value=32.768KHz
X2 "XTAL_4_PINS" CRY_NX1612SA_4P 54.759,32.135 r180 top value=40MHz

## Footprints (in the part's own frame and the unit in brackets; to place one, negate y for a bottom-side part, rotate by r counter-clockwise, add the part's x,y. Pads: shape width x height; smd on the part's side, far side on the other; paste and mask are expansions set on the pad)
C0201_H0P5 [mm] "MCD-01534"
  rect 0.4x0.5 smd mask+0.05: 1(-0.3,0) 2(0.3,0)
  body extent -0.35,-0.2 0.35,0.2, height 0.55
C0201_MURATA_GRM033_H0P3 [mm] "GRM033R60J105ME11"
  rect 0.35x0.35 smd mask+0.05: 1(-0.275,0) 2(0.275,0)
  body extent -0.32,-0.17 0.32,0.17, height 0.33
C0402 [mm]
  rect 0.51x0.56 smd mask+0.05: 1(-0.45,0) 2(0.45,0)
  body extent -0.5,-0.3 0.5,0.3, height 0.4
C0603 [mm]
  rect 0.64x0.89 smd mask+0.05: 1(-0.7,0) 2(0.7,0)
  silkscreen extent -1.05,-0.55 1.02,0.55, body extent -0.9,-0.5 0.9,0.5, height 1.4
C0805 [mm]
  rect 0.9x1.4 smd mask+0.05: 1(-0.85,0) 2(0.85,0)
  silkscreen extent -1.3,-0.77 1.3,0.77, body extent -1.1,-0.7 1.1,0.7, height 1.35
CON_MOLEX_53047-0210 [mm]
  oval 1x1.3 hole 0.5 mask+0.05: 1(-0.625,0) 2(0.625,0)
  silkscreen extent -2.12,-1.15 2.13,2.05, body extent -2.12,-1.15 2.13,2.05, height 4.2
CPOL_TCJ-B_1210_H210 [mm] "MCD-01791"
  rect 1.35x2.8 smd mask+0.05: 1(-1.375,0) 2(1.375,0)
  silkscreen extent -2.33,-1.68 1.85,1.68, body extent -1.85,-1.5 1.85,1.5, height 2.11
CRY_NX1612SA_4P [mm] "MCD-02262"
  rect 0.75x0.6 smd mask+0.038: 1(-0.525,-0.375) 2(0.525,-0.375) 3(0.525,0.375) 4(-0.525,0.375)
  silkscreen extent -1.02,-0.8 0.03,0.6, body extent -0.8,-0.6 0.8,0.6, height 0.51
CRY_NX2012SA_2P [mm]
  rect 1x1.25 smd mask+0.05: 1(-0.75,0) 2(0.75,0)
  silkscreen extent -1.05,-0.75 1.05,0.75, body extent -1.05,-0.63 1.05,0.63, height 0.6
DIO_SOD323 [mm]
  rect 1.06x0.54 smd mask+0.05: 1(-1.07,0) 2(1.07,0)
  silkscreen extent -0.9,-0.72 0.9,0.72, body extent -1.3,-0.78 1.3,0.78, height 1.17
DIO_SOT23 [mm]
  rect 1x1.4 smd mask+0.05: 1(-0.95,-1.1) 2(0.95,-1.1) 3(0,1.1)
  silkscreen extent -1.63,-0.82 1.63,0.82, body extent -1.56,-1.25 1.56,1.25, height 1.1
ICC_FBGA96_TB_7P5X13_P080 [mm] "MCD-03523"
  round 0.35 smd mask+0.05: A1(-3.2,6) A2(-2.4,6) A3(-1.6,6) A7(1.6,6) A8(2.4,6) A9(3.2,6) B1(-3.2,5.2) B2(-2.4,5.2) B3(-1.6,5.2) B7(1.6,5.2) B8(2.4,5.2) B9(3.2,5.2) C1(-3.2,4.4) C2(-2.4,4.4) C3(-1.6,4.4) C7(1.6,4.4) C8(2.4,4.4) C9(3.2,4.4) D1(-3.2,3.6) D2(-2.4,3.6) D3(-1.6,3.6) D7(1.6,3.6) D8(2.4,3.6) D9(3.2,3.6) E1(-3.2,2.8) E2(-2.4,2.8) E3(-1.6,2.8) E7(1.6,2.8) E8(2.4,2.8) E9(3.2,2.8) F1(-3.2,2) F2(-2.4,2) F3(-1.6,2) F7(1.6,2) F8(2.4,2) F9(3.2,2) G1(-3.2,1.2) G2(-2.4,1.2) G3(-1.6,1.2) G7(1.6,1.2) G8(2.4,1.2) G9(3.2,1.2) H1(-3.2,0.4) H2(-2.4,0.4) H3(-1.6,0.4) H7(1.6,0.4) H8(2.4,0.4) H9(3.2,0.4) J1(-3.2,-0.4) J2(-2.4,-0.4) J3(-1.6,-0.4) J7(1.6,-0.4) J8(2.4,-0.4) J9(3.2,-0.4) K1(-3.2,-1.2) K2(-2.4,-1.2) K3(-1.6,-1.2) K7(1.6,-1.2) K8(2.4,-1.2) K9(3.2,-1.2) L1(-3.2,-2) L2(-2.4,-2) L3(-1.6,-2) L7(1.6,-2) L8(2.4,-2) L9(3.2,-2) M1(-3.2,-2.8) M2(-2.4,-2.8) M3(-1.6,-2.8) M7(1.6,-2.8) M8(2.4,-2.8) M9(3.2,-2.8) N1(-3.2,-3.6) N2(-2.4,-3.6) N3(-1.6,-3.6) N7(1.6,-3.6) N8(2.4,-3.6) N9(3.2,-3.6) P1(-3.2,-4.4) P2(-2.4,-4.4) P3(-1.6,-4.4) P7(1.6,-4.4) P8(2.4,-4.4) P9(3.2,-4.4) R1(-3.2,-5.2) R2(-2.4,-5.2) R3(-1.6,-5.2) R7(1.6,-5.2) R8(2.4,-5.2) R9(3.2,-5.2) T1(-3.2,-6) T2(-2.4,-6) T3(-1.6,-6) T7(1.6,-6) T8(2.4,-6) T9(3.2,-6)
  silkscreen extent -3.93,-6.55 3.8,6.68, body extent -3.8,-6.55 3.8,6.55, height 1.21
ICC_P-WFBGA153_13X11P5_P050 [mm]
  round 0.23 smd mask+0.05: A1(-3.25,-3.25) A2(-3.25,-2.75) A3(-3.25,-2.25) A4(-3.25,-1.75) A5(-3.25,-1.25) A6(-3.25,-0.75) A7(-3.25,-0.25) A8(-3.25,0.25) A9(-3.25,0.75) A10(-3.25,1.25) A11(-3.25,1.75) A12(-3.25,2.25) A13(-3.25,2.75) A14(-3.25,3.25) B1(-2.75,-3.25) B2(-2.75,-2.75) B3(-2.75,-2.25) B4(-2.75,-1.75) B5(-2.75,-1.25) B6(-2.75,-0.75) B7(-2.75,-0.25) B8(-2.75,0.25) B9(-2.75,0.75) B10(-2.75,1.25) B11(-2.75,1.75) B12(-2.75,2.25) B13(-2.75,2.75) B14(-2.75,3.25) C1(-2.25,-3.25) C2(-2.25,-2.75) C3(-2.25,-2.25) C4(-2.25,-1.75) C5(-2.25,-1.25) C6(-2.25,-0.75) C7(-2.25,-0.25) C8(-2.25,0.25) C9(-2.25,0.75) C10(-2.25,1.25) C11(-2.25,1.75) C12(-2.25,2.25) C13(-2.25,2.75) C14(-2.25,3.25) D1(-1.75,-3.25) D2(-1.75,-2.75) D3(-1.75,-2.25) D4(-1.75,-1.75) D12(-1.75,2.25) D13(-1.75,2.75) D14(-1.75,3.25) E1(-1.25,-3.25) E2(-1.25,-2.75) E3(-1.25,-2.25) E5(-1.25,-1.25) E6(-1.25,-0.75) E7(-1.25,-0.25) E8(-1.25,0.25) E9(-1.25,0.75) E10(-1.25,1.25) E12(-1.25,2.25) E13(-1.25,2.75) E14(-1.25,3.25) F1(-0.75,-3.25) F2(-0.75,-2.75) F3(-0.75,-2.25) F5(-0.75,-1.25) F10(-0.75,1.25) F12(-0.75,2.25) F13(-0.75,2.75) F14(-0.75,3.25) G1(-0.25,-3.25) G2(-0.25,-2.75) G3(-0.25,-2.25) G5(-0.25,-1.25) G10(-0.25,1.25) G12(-0.25,2.25) G13(-0.25,2.75) G14(-0.25,3.25) H1(0.25,-3.25) H2(0.25,-2.75) H3(0.25,-2.25) H5(0.25,-1.25) H10(0.25,1.25) H12(0.25,2.25) H13(0.25,2.75) H14(0.25,3.25) J1(0.75,-3.25) J2(0.75,-2.75) J3(0.75,-2.25) J5(0.75,-1.25) J10(0.75,1.25) J12(0.75,2.25) J13(0.75,2.75) J14(0.75,3.25) K1(1.25,-3.25) K2(1.25,-2.75) K3(1.25,-2.25) K5(1.25,-1.25) K6(1.25,-0.75) K7(1.25,-0.25) K8(1.25,0.25) K9(1.25,0.75) K10(1.25,1.25) K12(1.25,2.25) K13(1.25,2.75) K14(1.25,3.25) L1(1.75,-3.25) L2(1.75,-2.75) L3(1.75,-2.25) L12(1.75,2.25) L13(1.75,2.75) L14(1.75,3.25) M1(2.25,-3.25) M2(2.25,-2.75) M3(2.25,-2.25) M4(2.25,-1.75) M5(2.25,-1.25) M6(2.25,-0.75) M7(2.25,-0.25) M8(2.25,0.25) M9(2.25,0.75) M10(2.25,1.25) M11(2.25,1.75) M12(2.25,2.25) M13(2.25,2.75) M14(2.25,3.25) N1(2.75,-3.25) N2(2.75,-2.75) N3(2.75,-2.25) N4(2.75,-1.75) N5(2.75,-1.25) N6(2.75,-0.75) N7(2.75,-0.25) N8(2.75,0.25) N9(2.75,0.75) N10(2.75,1.25) N11(2.75,1.75) N12(2.75,2.25) N13(2.75,2.75) N14(2.75,3.25) P1(3.25,-3.25) P2(3.25,-2.75) P3(3.25,-2.25) P4(3.25,-1.75) P5(3.25,-1.25) P6(3.25,-0.75) P7(3.25,-0.25) P8(3.25,0.25) P9(3.25,0.75) P10(3.25,1.25) P11(3.25,1.75) P12(3.25,2.25) P13(3.25,2.75) P14(3.25,3.25)
  silkscreen extent -6.78,-6.02 6.63,5.87, body extent -6.55,-5.8 6.55,5.8, height 1
ICC_QFN56-EPAD_6P5X6P5_P040 [mm] "MCD-03000"
  rect 0.55x0.21 smd mask+0.05: 1(-3.245,2.6) 14(-3.245,-2.6) 29(3.245,-2.6) 42(3.245,2.6)
  rect 0.7x0.21 smd mask+0.05: 2(-3.17,2.2) 3(-3.17,1.8) 4(-3.17,1.4) 5(-3.17,1) 6(-3.17,0.6) 7(-3.17,0.2) 8(-3.17,-0.2) 9(-3.17,-0.6) 10(-3.17,-1) 11(-3.17,-1.4) 12(-3.17,-1.8) 13(-3.17,-2.2) 30(3.17,-2.2) 31(3.17,-1.8) 32(3.17,-1.4) 33(3.17,-1) 34(3.17,-0.6) 35(3.17,-0.2) 36(3.17,0.2) 37(3.17,0.6) 38(3.17,1) 39(3.17,1.4) 40(3.17,1.8) 41(3.17,2.2)
  rect 0.21x0.55 smd mask+0.05: 15(-2.6,-3.245) 28(2.6,-3.245) 43(2.6,3.245) 56(-2.6,3.245)
  rect 0.21x0.7 smd mask+0.05: 16(-2.2,-3.17) 17(-1.8,-3.17) 18(-1.4,-3.17) 19(-1,-3.17) 20(-0.6,-3.17) 21(-0.2,-3.17) 22(0.2,-3.17) 23(0.6,-3.17) 24(1,-3.17) 25(1.4,-3.17) 26(1.8,-3.17) 27(2.2,-3.17) 44(2.2,3.17) 45(1.8,3.17) 46(1.4,3.17) 47(1,3.17) 48(0.6,3.17) 49(0.2,3.17) 50(-0.2,3.17) 51(-0.6,3.17) 52(-1,3.17) 53(-1.4,3.17) 54(-1.8,3.17) 55(-2.2,3.17)
  rect 4.7x4.7 smd mask+0.05: 57(0,0)
  Top Layer region: -2.495,-2.97 -2.495,-2.82 -2.555,-2.82 -2.705,-2.97
  Top Layer region: 2.495,2.97 2.495,2.82 2.555,2.82 2.705,2.97
  Top Layer region: 2.97,2.495 2.82,2.495 2.82,2.555 2.97,2.705
  Top Layer region: 2.495,-2.97 2.495,-2.82 2.555,-2.82 2.705,-2.97
  Top Layer region: 2.97,-2.495 2.82,-2.495 2.82,-2.555 2.97,-2.705
  Top Layer region: -2.495,2.97 -2.495,2.82 -2.555,2.82 -2.705,2.97
  Top Layer region: -2.97,-2.495 -2.82,-2.495 -2.82,-2.555 -2.97,-2.705
  Top Layer region: -2.97,2.495 -2.82,2.495 -2.82,2.555 -2.97,2.705
  silkscreen extent -3.44,3 -3.01,3.42, body extent -3.25,-3.25 3.25,3.25, height 0.91
ICC_TFBGA424_14X14_P050_H1P20_CODE-B0A2 [mm] "MCD_03375"
  round 0.23 smd paste+0.025 mask+0.05: 1A1(-2.75,2.75) 1A3(-1.75,2.75) 1A5(-0.75,2.75) 1A7(0.25,2.75) 1A9(1.25,2.75) 1A11(2.25,2.75) 1B2(-2.25,2.25) 1B4(-1.25,2.25) 1B6(-0.25,2.25) 1B8(0.75,2.25) 1B10(1.75,2.25) 1B12(2.75,2.25) 1C1(-2.75,1.75) 1C3(-1.75,1.75) 1C5(-0.75,1.75) 1C7(0.25,1.75) 1C9(1.25,1.75) 1C11(2.25,1.75) 1D2(-2.25,1.25) 1D4(-1.25,1.25) 1D6(-0.25,1.25) 1D8(0.75,1.25) 1D10(1.75,1.25) 1D12(2.75,1.25) 1E1(-2.75,0.75) 1E3(-1.75,0.75) 1E5(-0.75,0.75) 1E7(0.25,0.75) 1E9(1.25,0.75) 1E11(2.25,0.75) 1F2(-2.25,0.25) 1F4(-1.25,0.25) 1F6(-0.25,0.25) 1F8(0.75,0.25) 1F10(1.75,0.25) 1F12(2.75,0.25) 1G1(-2.75,-0.25) 1G3(-1.75,-0.25) 1G5(-0.75,-0.25) 1G7(0.25,-0.25) 1G9(1.25,-0.25) 1G11(2.25,-0.25) 1H2(-2.25,-0.75) 1H4(-1.25,-0.75) 1H6(-0.25,-0.75) 1H8(0.75,-0.75) 1H10(1.75,-0.75) 1H12(2.75,-0.75) 1J1(-2.75,-1.25) 1J3(-1.75,-1.25) 1J5(-0.75,-1.25) 1J7(0.25,-1.25) 1J9(1.25,-1.25) 1J11(2.25,-1.25) 1K2(-2.25,-1.75) 1K4(-1.25,-1.75) 1K6(-0.25,-1.75) 1K8(0.75,-1.75) 1K10(1.75,-1.75) 1K12(2.75,-1.75) 1L1(-2.75,-2.25) 1L3(-1.75,-2.25) 1L5(-0.75,-2.25) 1L7(0.25,-2.25) 1L9(1.25,-2.25) 1L11(2.25,-2.25) 1M2(-2.25,-2.75) 1M4(-1.25,-2.75) 1M6(-0.25,-2.75) 1M8(0.75,-2.75) 1M10(1.75,-2.75) 1M12(2.75,-2.75) A1(-6.5,6.5) A2(-6,6.5) A3(-5.5,6.5) A6(-4,6.5) A7(-3.5,6.5) A10(-2,6.5) A11(-1.5,6.5) A14(0,6.5) A15(0.5,6.5) A18(2,6.5) A19(2.5,6.5) A22(4,6.5) A23(4.5,6.5) A26(6,6.5) A27(6.5,6.5) AA1(-6.5,-3.5) AA2(-6,-3.5) AA3(-5.5,-3.5) AA5(-4.5,-3.5) AA7(-3.5,-3.5) AA9(-2.5,-3.5) AA11(-1.5,-3.5) AA13(-0.5,-3.5) AA15(0.5,-3.5) AA17(1.5,-3.5) AA19(2.5,-3.5) AA21(3.5,-3.5) AA23(4.5,-3.5) AA25(5.5,-3.5) AA26(6,-3.5) AB1(-6.5,-4) AB2(-6,-4) AB3(-5.5,-4) AB4(-5,-4) AB6(-4,-4) AB8(-3,-4) AB10(-2,-4) AB12(-1,-4) AB14(0,-4) AB16(1,-4) AB18(2,-4) AB20(3,-4) AB22(4,-4) AB24(5,-4) AB25(5.5,-4) AB26(6,-4) AB27(6.5,-4) AC2(-6,-4.5) AC3(-5.5,-4.5) AC5(-4.5,-4.5) AC7(-3.5,-4.5) AC9(-2.5,-4.5) AC11(-1.5,-4.5) AC13(-0.5,-4.5) AC15(0.5,-4.5) AC17(1.5,-4.5) AC19(2.5,-4.5) AC21(3.5,-4.5) AC23(4.5,-4.5) AC25(5.5,-4.5) AC26(6,-4.5) AC27(6.5,-4.5) AD3(-5.5,-5) AD4(-5,-5) AD6(-4,-5) AD8(-3,-5) AD10(-2,-5) AD12(-1,-5) AD14(0,-5) AD16(1,-5) AD18(2,-5) AD20(3,-5) AD22(4,-5) AD24(5,-5) AD25(5.5,-5) AE1(-6.5,-5.5) AE2(-6,-5.5) AE3(-5.5,-5.5) AE4(-5,-5.5) AE5(-4.5,-5.5) AE6(-4,-5.5) AE7(-3.5,-5.5) AE8(-3,-5.5) AE9(-2.5,-5.5) AE10(-2,-5.5) AE11(-1.5,-5.5) AE12(-1,-5.5) AE13(-0.5,-5.5) AE14(0,-5.5) AE15(0.5,-5.5) AE16(1,-5.5) AE17(1.5,-5.5) AE18(2,-5.5) AE19(2.5,-5.5) AE20(3,-5.5) AE21(3.5,-5.5) AE22(4,-5.5) AE23(4.5,-5.5) AE24(5,-5.5) AE25(5.5,-5.5) AE26(6,-5.5) AF1(-6.5,-6) AF2(-6,-6) AF3(-5.5,-6) AF5(-4.5,-6) AF6(-4,-6) AF7(-3.5,-6) AF9(-2.5,-6) AF10(-2,-6) AF11(-1.5,-6) AF13(-0.5,-6) AF14(0,-6) AF15(0.5,-6) AF17(1.5,-6) AF18(2,-6) AF19(2.5,-6) AF21(3.5,-6) AF22(4,-6) AF23(4.5,-6) AF25(5.5,-6) AF26(6,-6) AF27(6.5,-6) AG1(-6.5,-6.5) AG2(-6,-6.5) AG5(-4.5,-6.5) AG6(-4,-6.5) AG9(-2.5,-6.5) AG10(-2,-6.5) AG13(-0.5,-6.5) AG14(0,-6.5) AG17(1.5,-6.5) AG18(2,-6.5) AG21(3.5,-6.5) AG22(4,-6.5) AG25(5.5,-6.5) AG26(6,-6.5) AG27(6.5,-6.5) B1(-6.5,6) B2(-6,6) B3(-5.5,6) B5(-4.5,6) B6(-4,6) B7(-3.5,6) B9(-2.5,6) B10(-2,6) B11(-1.5,6) B13(-0.5,6) B14(0,6) B15(0.5,6) B17(1.5,6) B18(2,6) B19(2.5,6) B21(3.5,6) B22(4,6) B23(4.5,6) B25(5.5,6) B26(6,6) B27(6.5,6) C2(-6,5.5) C3(-5.5,5.5) C4(-5,5.5) C5(-4.5,5.5) C6(-4,5.5) C7(-3.5,5.5) C8(-3,5.5) C9(-2.5,5.5) C10(-2,5.5) C11(-1.5,5.5) C12(-1,5.5) C13(-0.5,5.5) C14(0,5.5) C15(0.5,5.5) C16(1,5.5) C17(1.5,5.5) C18(2,5.5) C19(2.5,5.5) C20(3,5.5) C21(3.5,5.5) C22(4,5.5) C23(4.5,5.5) C24(5,5.5) C25(5.5,5.5) C26(6,5.5) C27(6.5,5.5) D3(-5.5,5) D4(-5,5) D6(-4,5) D8(-3,5) D10(-2,5) D12(-1,5) D14(0,5) D16(1,5) D18(2,5) D20(3,5) D22(4,5) D24(5,5) D25(5.5,5) E1(-6.5,4.5) E2(-6,4.5) E3(-5.5,4.5) E5(-4.5,4.5) E7(-3.5,4.5) E9(-2.5,4.5) E11(-1.5,4.5) E13(-0.5,4.5) E15(0.5,4.5) E17(1.5,4.5) E19(2.5,4.5) E21(3.5,4.5) E23(4.5,4.5) E25(5.5,4.5) E26(6,4.5) F1(-6.5,4) F2(-6,4) F3(-5.5,4) F4(-5,4) F6(-4,4) F8(-3,4) F10(-2,4) F12(-1,4) F14(0,4) F16(1,4) F18(2,4) F20(3,4) F22(4,4) F24(5,4) F25(5.5,4) F26(6,4) F27(6.5,4) G2(-6,3.5) G3(-5.5,3.5) G5(-4.5,3.5) G7(-3.5,3.5) G9(-2.5,3.5) G11(-1.5,3.5) G13(-0.5,3.5) G15(0.5,3.5) G17(1.5,3.5) G19(2.5,3.5) G21(3.5,3.5) G23(4.5,3.5) G25(5.5,3.5) G26(6,3.5) G27(6.5,3.5) H3(-5.5,3) H4(-5,3) H6(-4,3) H22(4,3) H24(5,3) H25(5.5,3) J1(-6.5,2.5) J2(-6,2.5) J3(-5.5,2.5) J5(-4.5,2.5) J7(-3.5,2.5) J21(3.5,2.5) J23(4.5,2.5) J25(5.5,2.5) J26(6,2.5) K1(-6.5,2) K2(-6,2) K3(-5.5,2) K4(-5,2) K6(-4,2) K22(4,2) K24(5,2) K25(5.5,2) K26(6,2) K27(6.5,2) L2(-6,1.5) L3(-5.5,1.5) L5(-4.5,1.5) L7(-3.5,1.5) L21(3.5,1.5) L23(4.5,1.5) L25(5.5,1.5) L26(6,1.5) L27(6.5,1.5) M3(-5.5,1) M4(-5,1) M6(-4,1) M22(4,1) M24(5,1) M25(5.5,1) N1(-6.5,0.5) N2(-6,0.5) N3(-5.5,0.5) N5(-4.5,0.5) N7(-3.5,0.5) N21(3.5,0.5) N23(4.5,0.5) N25(5.5,0.5) N26(6,0.5) P1(-6.5,0) P2(-6,0) P3(-5.5,0) P4(-5,0) P6(-4,0) P22(4,0) P24(5,0) P25(5.5,0) P26(6,0) P27(6.5,0) R2(-6,-0.5) R3(-5.5,-0.5) R5(-4.5,-0.5) R7(-3.5,-0.5) R21(3.5,-0.5) R23(4.5,-0.5) R25(5.5,-0.5) R26(6,-0.5) R27(6.5,-0.5) T3(-5.5,-1) T4(-5,-1) T6(-4,-1) T22(4,-1) T24(5,-1) T25(5.5,-1) U1(-6.5,-1.5) U2(-6,-1.5) U3(-5.5,-1.5) U5(-4.5,-1.5) U7(-3.5,-1.5) U21(3.5,-1.5) U23(4.5,-1.5) U25(5.5,-1.5) U26(6,-1.5) V1(-6.5,-2) V2(-6,-2) V3(-5.5,-2) V4(-5,-2) V6(-4,-2) V22(4,-2) V24(5,-2) V25(5.5,-2) V26(6,-2) V27(6.5,-2) W2(-6,-2.5) W3(-5.5,-2.5) W5(-4.5,-2.5) W7(-3.5,-2.5) W21(3.5,-2.5) W23(4.5,-2.5) W25(5.5,-2.5) W26(6,-2.5) W27(6.5,-2.5) Y3(-5.5,-3) Y4(-5,-3) Y6(-4,-3) Y22(4,-3) Y24(5,-3) Y25(5.5,-3)
  silkscreen extent -7.17,-7 7,7.17, body extent -7,-7 7,7, height 1.21
IND_2016_MURATA_LQM2MPN2R2NG0 [mm]
  rect 0.8x1.8 smd mask+0.05: 1(-0.8,0) 2(0.8,0)
  silkscreen extent -0.28,-0.87 0.28,0.87, body extent -1.07,-0.87 1.08,0.87, height 1
IND_2520_TOKO_DFE252012P [mm]
  rect 0.8x2 smd mask+0.05: 1(-1,0) 2(1,0)
  silkscreen extent -1.35,-1.12 1.35,1.12, body extent -1.35,-1.1 1.35,1.1, height 2
LED_0603_OSRAM_LG-Q396-PS-35_GREEN_1A2K_H0P4 [mm]
  rect 0.8x0.8 smd mask+0.05: 1(-0.75,0) 2(0.75,0)
  silkscreen extent -0.85,-0.53 1.28,0.53, body extent -0.85,-0.45 0.85,0.45, height 0.6
LINK200 [mm]
  rect 0.2x0.35 smd paste-10 mask+0.05: 1(0,-0.225) 2(0,0.225)
R0201_H0P23 [mm] "MCD-00702"
  rect 0.4x0.5 smd mask+0.05: 1(-0.3,0) 2(0.3,0)
  body extent -0.32,-0.17 0.32,0.17, height 0.26
R0402 [mm]
  rect 0.51x0.7 smd mask+0.05: 1(-0.45,0) 2(0.45,0)
  body extent -0.52,-0.3 0.52,0.3, height 0.4
R0603 [mm]
  rect 0.64x1 smd mask+0.05: 1(-0.7,0) 2(0.7,0)
  silkscreen extent -1.05,-0.58 1.05,0.58, body extent -0.9,-0.5 0.9,0.5, height 0.56
SWI_WE_434121025816 [mm] "MCD-03492"
  rect 1.5x1.4 smd: 1(-3.25,0) 2(3.25,0)
  silkscreen extent -3,-1.95 3,1.95, body extent -3.65,-1.95 3.65,1.95, height 2.51
TP_SMD_1MM [mm]
  round 1 smd paste-10 mask+0.05: 1(0,0)
  silkscreen extent -0.7,-0.7 0.7,0.7

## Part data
B2: library part MCD-03492, "Switch tactile, SPST-NO, 50mA, 12V, 6x3.8mm", Manufacturer="WURTH ELEKTRONIC", Manufacturer_Part_Number=434121025816, Package=6x3.8mm
C1 C2 C3 C4 C5 C6 C7 C8 C10 C11 C12 C13 C44 C45 C46 C47 C48 C49 C50 C51 C52 C58 C59 C64 C68 C69 C70 C71 C72 C74 C75 C76 C77 C82: library part MCD-02377, "Capacitor, MLCC, 1uF, 6.3V, X5R, +/-20%, 0201, T=0,3mm", Manufacturer=MURATA, Manufacturer_Part_Number=GRM033R60J105MEA2, Package=0201
C9 C53 C54 C55 C56 C60 C61 C62 C63 C65 C66 C67 C83 C84 C85 C118 C130 C146 C147 C148 C149 C151 C158 C162 C170 C185 C197 C198 C203 C205 C212 C213 C214 C215 C216 C218 C219 C221: library part MCD-00006, "Capacitor, MLCC, 100nF, 16V, X7R, +/-10%, 0402, T=0.5mm", Alternate_Manufacturer=MURATA, Alternate_Manufacturer_Part_Number=GCM155R71C104KA55D, Manufacturer=YAGEO, Manufacturer_Part_Number=CC0402KRX7R7BB104, Package=0402
C14: library part MCD-01823, "Capacitor, MLCC, 2.2uF, 6V3, X5R,+/-10%, 0402, T=0.5mm", Alternate_Manufacturer=N/A, Manufacturer=MURATA, Manufacturer_Part_Number=GRM155R60J225KE95D, Package=0402
C15 C250 C252 C260: library part MCD-02377, "Capacitor, MLCC, 1uF, 6.3V, X5R, +/-20%, 0201, T=0,3mm", Alternate_Manufacturer=N/A, Manufacturer=MURATA, Manufacturer_Part_Number=GRM033R60J105MEA2, Package=0201
C16 C17 C192 C195 C196 C201 C220 C234 C236 C237 C238 C239 C240 C244 C246 C248 C251 C253: library part MCD-01535, "Capacitor, MLCC,100nF, 10V, X7R, +/-10%, 0201, T=0.3mm", Alternate_Manufacturer=N/A, Manufacturer=MURATA, Manufacturer_Part_Number=GRM033R61A104KE15, Package=0201
C18 C42: library part MCD-01796, "Capacitor, Tantalum, 100uF, 6V3, 40mR, +/-20%,  Type_B (3528 metric), T=1.9mm", Manufacturer=AVX, Manufacturer_Part_Number=TCJB107M006R0040, Package="3528 (metric)"
C19 C21 C152 C157 C186 C187 C193 C204 C206 C207: library part MCD-03139, "Capacitor, MLCC, 22uF, 10V, X5R, +/-20%, 0805, T=1,25mm", Manufacturer=MURATA, Manufacturer_Part_Number=GRM21BR61A226ME51L, Package=0805
C20 C29 C30 C32 C38 C184 C199: library part MCD-00099, "Capacitor, MLCC, 10uF, 10V, X5R, +/-10%, 0603, T=0,8mm", Alternate_Manufacturer=N/A, Manufacturer=MURATA, Manufacturer_Part_Number=GRM188R61A106KE69D, Package=0603
C22 C23 C24 C26 C27 C28 C34 C35 C36 C37 C41 C145 C183 C200 C202 C211: library part MCD-00100, "Capacitor, MLCC, 22uF, 6V3, X5R, +/-20%, 0603, T=0,8mm", Alternate_Manufacturer=N/A, Manufacturer=MURATA, Manufacturer_Part_Number=GRM188R60J226MEA0J, Package=0603
C33: library part MCD-00011, "Capacitor, MLCC, 10nF, 16V, X7R, 10%, 0402, T=0.5mm", Manufacturer=YAGEO, Manufacturer_Part_Number=CC0402KRX7R7BB103, Package=C0402
C39 C40: library part MCD-03140, "Capacitor, MLCC, 10uF, 6.3V, X5R, +/-20%, 0402, T=0.5mm", Manufacturer=MURATA, Manufacturer_Part_Number=GRM155R60J106ME05D, Package=0402
C43 C153 C154 C188: library part MCD-00095, "Capacitor, MLCC, 1uF, 25V, X5R, +/-10%, 0402, T=0.5mm", Manufacturer=MURATA, Manufacturer_Part_Number=GRM155R61E105KA12, Package=0402
C73 C88 C150 C194: library part MCD-01341, "Capacitor, MLCC, 10uF, 6V3, X5R, +/-20%, 0603, T=0,8mm", Alternate_Manufacturer=MURATA, Alternate_Manufacturer_Part_Number=GRM188R60J106ME84D, Manufacturer_Part_Number=GRM188R60J106ME47D, Package=0603
C79 C117 C128: library part MCD-02606, "Capacitor, MLCC, 2.2uF, 6.3V, X5R, +/-10%, 0402, T=0.5mm", Manufacturer=YAGEO, Manufacturer_Part_Number=CC0402KRX5R5BB225, Package=0402
C81 C86 C90 C92: library part MCD-00674, "Capacitor, MLCC, 6.8pF, 50V, NPO, +-0.25pF, 0402, T=0.5mm", Alternate_Manufacturer=N/A, Manufacturer=YAGEO, Manufacturer_Part_Number=CC0402CRNPO9BN6R8, Package=0402
C87: library part MCD-00006, "Capacitor,100nF,16V,X7R,10%,0402", Alternate_Manufacturer=MURATA, Alternate_Manufacturer_Part_Number=GCM155R71C104KA55D, Manufacturer=YAGEO, Manufacturer_Part_Number=CC0402KRX7R7BB104, Package=0402
C91 C142 C156 C189 C190 C208 C209 C217 C1141: library part MCD-01356, "Capacitor, MLCC, 4.7uF, 6V3, X5R, +/-20%, 0402, T=0.5mm", Manufacturer=MURATA, Manufacturer_Part_Number=GRM155R60J475ME47, Package=0402
C155: library part MCD-02198, "Capacitor, MLCC, 10nF, 50V, X7R, +/-10%, 0402, T=0.5mm", Manufacturer=YAGEO, Manufacturer_Part_Number=CC0402KRX7R9BB103, Package=0402
C225: library part MCD-01534, "Capacitor, MLCC, 4,7uF, 6V3, X5R, +/-20%, 0201, T=0.5mm", Alternate_Manufacturer=N/A, Manufacturer=MURATA, Manufacturer_Part_Number=GRM035R60J475ME15, Package=0201
C235: library part MCD-02235, "Capacitor, MLCC, 2.2uF, 10V, X5R,+/-10%, 0201, T=0.5mm", Manufacturer=MURATA, Manufacturer_Part_Number=GRM033R61A225KE47D, Package=0201
CN12: library part MCD-00655, "Header 2 circuits, 1.25mm Pitch ,  Vertical, with Friction Lock", Alternate_Manufacturer=N/A, Manufacturer=MOLEX, Manufacturer_Part_Number=53047-0210
D6: library part MCD-03280, "Diode, Schottky, Dual Common Cathode, 0V3, 300mA, 40V, SOT-23", Manufacturer=STMICROELECTRONICS, Manufacturer_Part_Number=BAT54CFILM, Package=SOT-23
D7: library part MCD-00034, Manufacturer=STMICROELECTRONICS, Manufacturer_HQ_COO=EU
L1 L6: library part MCD-03143, "Inductor, 2.2uH, +/-20%, Itemp= 1700mA, Isat= 2400mA, 0R140, 0806, T=1mm", Manufacturer=MURATA, Manufacturer_Part_Number=DFE201610E-2R2M{}P2, Package=0806
L2 L4: library part MCD-03142, "Inductor, 0.68uH, +/-20%, Itemp= 3900mA, Isat= 5400mA, 0R031, 1008, T=1.2mm", Manufacturer=MURATA, Manufacturer_Part_Number=DFE252012F-R68M{}P2, Package=1008
L3 L5 L7: library part MCD-03141, "Inductor, 0.68uH, +/-20%, Itemp= 3100mA, Isat= 4300mA, 0R043, 0806, T=1mm", Manufacturer=MURATA, Manufacturer_Part_Number=DFE201610E-R68M{}P2, Package=0806
LD11: library part MCD-00588, "LED Green, 0603 SMD, Forward Voltage Typ=2V, Max=2.5V", Alternate_Manufacturer="VISHAY SEMICONDUCTOR OPTO DIVISION", Alternate_Manufacturer_Part_Number=VLMTG1300-GS08, Manufacturer="OSRAM OPTO SEMICONDUCTORS", Manufacturer_Part_Number="LG Q396-PS-35", Package="LED 0603"
LNK1 LNK2 LNK4 LNK7 LNK8 LNK11: library part MCD-02777, "Track link on PCB 200um width for layout routing", Manufacturer=N/A
R2 R3 R46 R57 R59 R60 R64 R81 R267 R269 R286: library part MCD-00052, "Resistor,0R,0402,5%,1/16W", Alternate_Manufacturer=N/A, Manufacturer=YAGEO, Manufacturer_Part_Number=RC0402JR-070RL, Package=0402
R11: library part MCD-00056, "Resistor, 0R, 0603, +/-5%, 1/10W", Manufacturer=YAGEO, Manufacturer_Part_Number=RC0603JR-070RL, Package=0603
R27 R163 R272: library part MCD-00053, "Resistor,10K,0402,1%,1/16W", Alternate_Manufacturer=N/A, Manufacturer=YAGEO, Manufacturer_Part_Number=RC0402FR-0710KL, Package=0402
R62 R75 R174: library part MCD-02253, "Resistor,240R,0201,1%,1/20W", Alternate_Manufacturer=N/A, Manufacturer=YAGEO, Manufacturer_Part_Number=RC0201FR-07240RL, Package=R0201
R66: library part MCD-00058, "Resistor, 20R, 0402, +/-1%, 1/16W", Alternate_Manufacturer=N/A, Manufacturer=YAGEO, Manufacturer_Part_Number=RC0402FR-0720RL, Package=0402
R67: library part MCD-00052, "Resistor, 0R, 0402, +/-5%, 1/16W", Manufacturer=YAGEO, Manufacturer_Part_Number=RC0402JR-070RL, Package=0402
R101 R103 R104 R248: library part MCD-00053, "Resistor,10K,0402,1%,1/16W", Manufacturer=YAGEO, Manufacturer_Part_Number=RC0402FR-0710KL, Package=0402
R141 R142 R146 R147: library part MCD-00061, "Resistor, 1K, 0402, +/-1%,1/16W", Manufacturer=YAGEO, Manufacturer_Part_Number=RC0402FR-071KL, Package=0402
R165 R166 R167 R168 R169 R170 R171 R175 R176 R177 R178 R180 R182 R183 R185 R186 R187 R188 R189 R190 R191 R192 R193 R194: library part MCD-00054, "Resistor, 56R, 0402, +/-1%, 1/16W", Alternate_Manufacturer=N/A, Manufacturer=YAGEO, Manufacturer_Part_Number=RC0402FR-0756RL, Package=0402
R181: library part MCD-01819, "Resistor,100R,0402,0,5%,1/16W,±100ppm/°C", Alternate_Manufacturer=N/A, Manufacturer=YAGEO, Manufacturer_Part_Number=RC0402DR-07100RL, Package=0402
R210: library part MCD-00441, "Resistor,270R,0402,1%,1/16W", Manufacturer=YAGEO, Manufacturer_Part_Number=RC0402FR-07270RL, Package=0402
R260 R261: library part MCD-00068, "Resistor,1K5,0402,1%,1/16W", Manufacturer=YAGEO, Manufacturer_Part_Number=RC0402FR-071K5L, Package=0402
TP21: library part MCD-00074, "Test Point 1mm", Manufacturer=n/a
U1: library part MCD-03375, "MPU , 2xCortex-A35@1.5GHz, Cortex-M33@400MHz, TFBGA 14x14, pitch 0.5, 648KB SRAM, With Crypto", Manufacturer=STMICROELECTRONICS, Package=TFBGA
U13 U15: library part MCD-03523, "Memory, DDR4 SDRAM, 1V2, 16Gbit, FBGA96", Manufacturer=MICRON, Package=FBGA-96
U26: library part MCD-03000, "STPMIC2", Manufacturer=STMICROELECTRONICS, Package=VQFN
U37: library part MCD-02799, "Memory, eMMC, 4GB, 15nm ,WFBGA , 153 pins", Manufacturer=KIOXIA, Manufacturer_Part_Number=THGBMTG5D1LBAIL, Package=WFBGA153
X1: library part MCD-01479, "Crystal, 32.768kHz, 6pF, +/-20ppm, 80K, 2.05x1.2mm", Manufacturer=NDK, Manufacturer_Part_Number=NX2012SA-32.768KHZ-EXS00A-MU00527, Package=2.05x1.2mm
X2: library part MCD-02344, "Crystal, 40MHz, 6pF, +/-20ppm, 80R, 1.6x1.2mm", Manufacturer=NDK, Manufacturer_Part_Number=NX1612SA-40MHZ-EXS00A-CS13836, Package=1.6x1.2mm

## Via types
v1: diameter 0.55, hole 0.35, Top Layer to Bottom Layer, 256 vias
v2: diameter 0.4, hole 0.2, Top Layer to Bottom Layer, tented both sides, 235 vias
v3: diameter 0.5, hole 0.2, Top Layer to Bottom Layer, 146 vias
v4: diameter 0.5, hole 0.25, Top Layer to Bottom Layer, 143 vias
v5: diameter 0.5, hole 0.25, Top Layer to Bottom Layer, tented both sides, 4 vias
